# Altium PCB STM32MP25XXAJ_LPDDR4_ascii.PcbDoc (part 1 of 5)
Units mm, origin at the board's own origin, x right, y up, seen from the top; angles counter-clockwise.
Board outline 172 x 137 mm, 4 copper layers (Top Layer, Signal Layer 1, Signal Layer 2, Bottom Layer), stack 1.614 mm thick; 188 components, 294 nets, 1141 pads, 872 vias.
Unrouted connection lines stored in the file: 13.
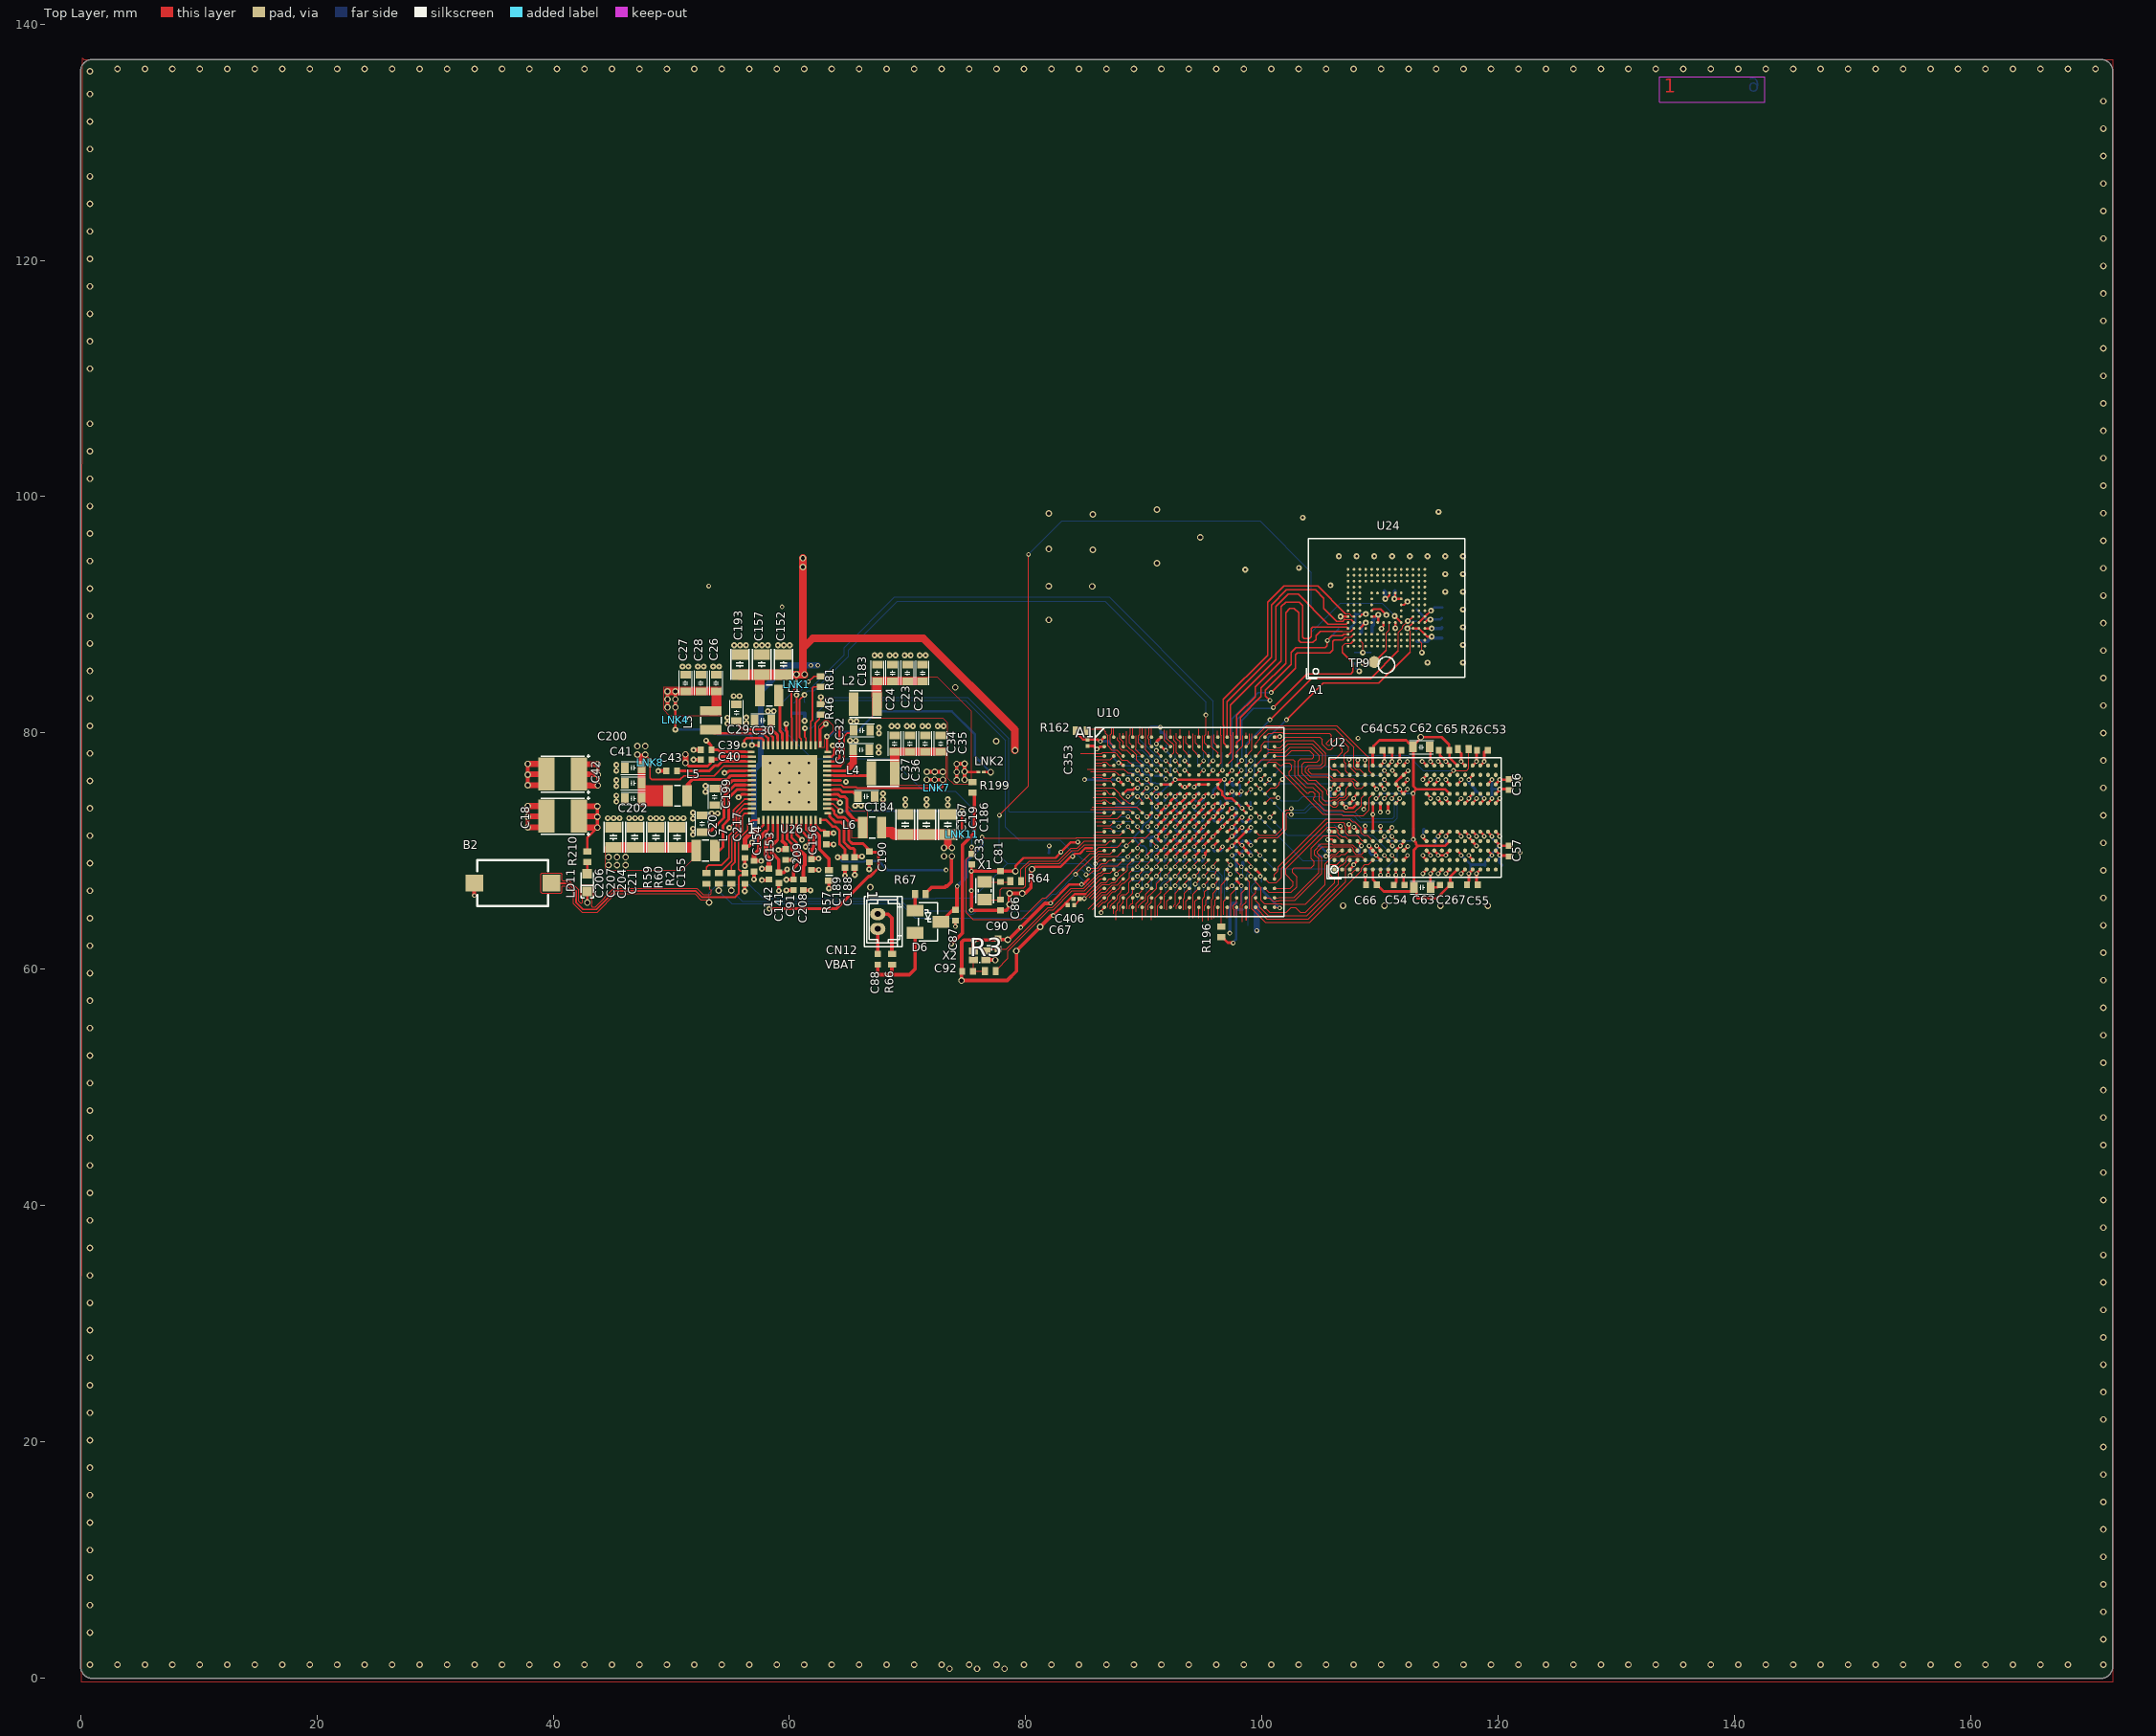
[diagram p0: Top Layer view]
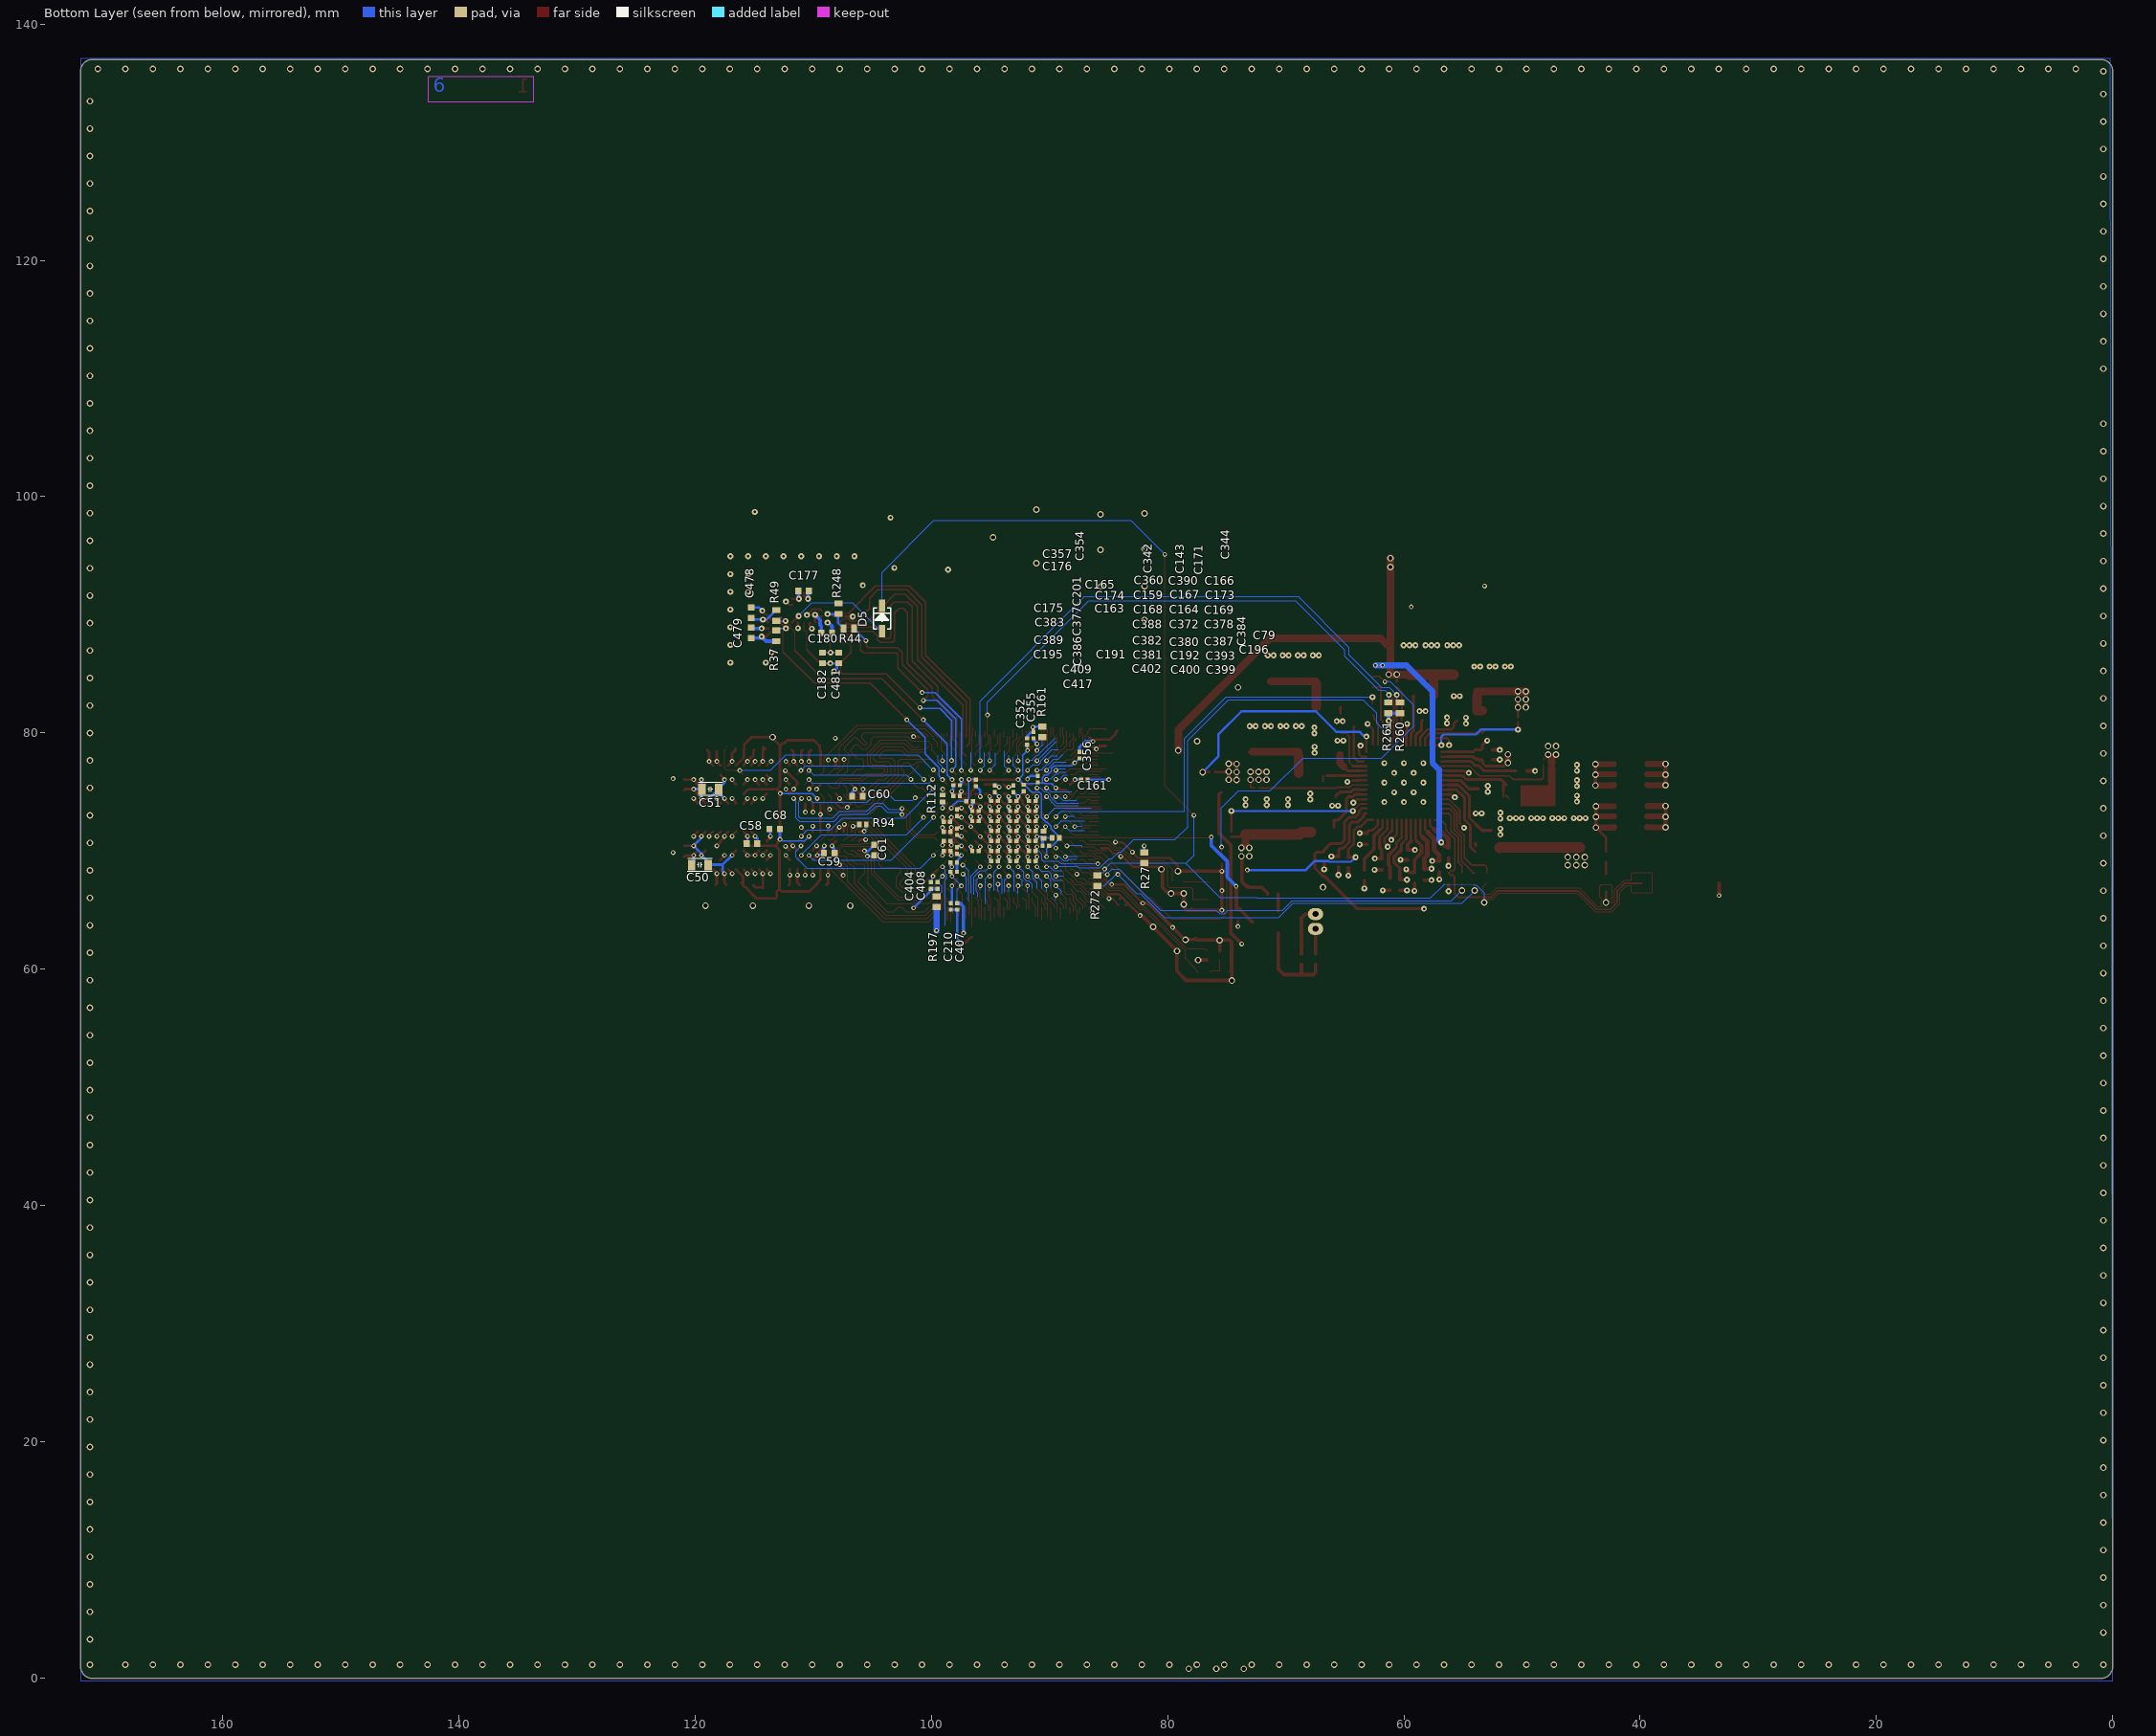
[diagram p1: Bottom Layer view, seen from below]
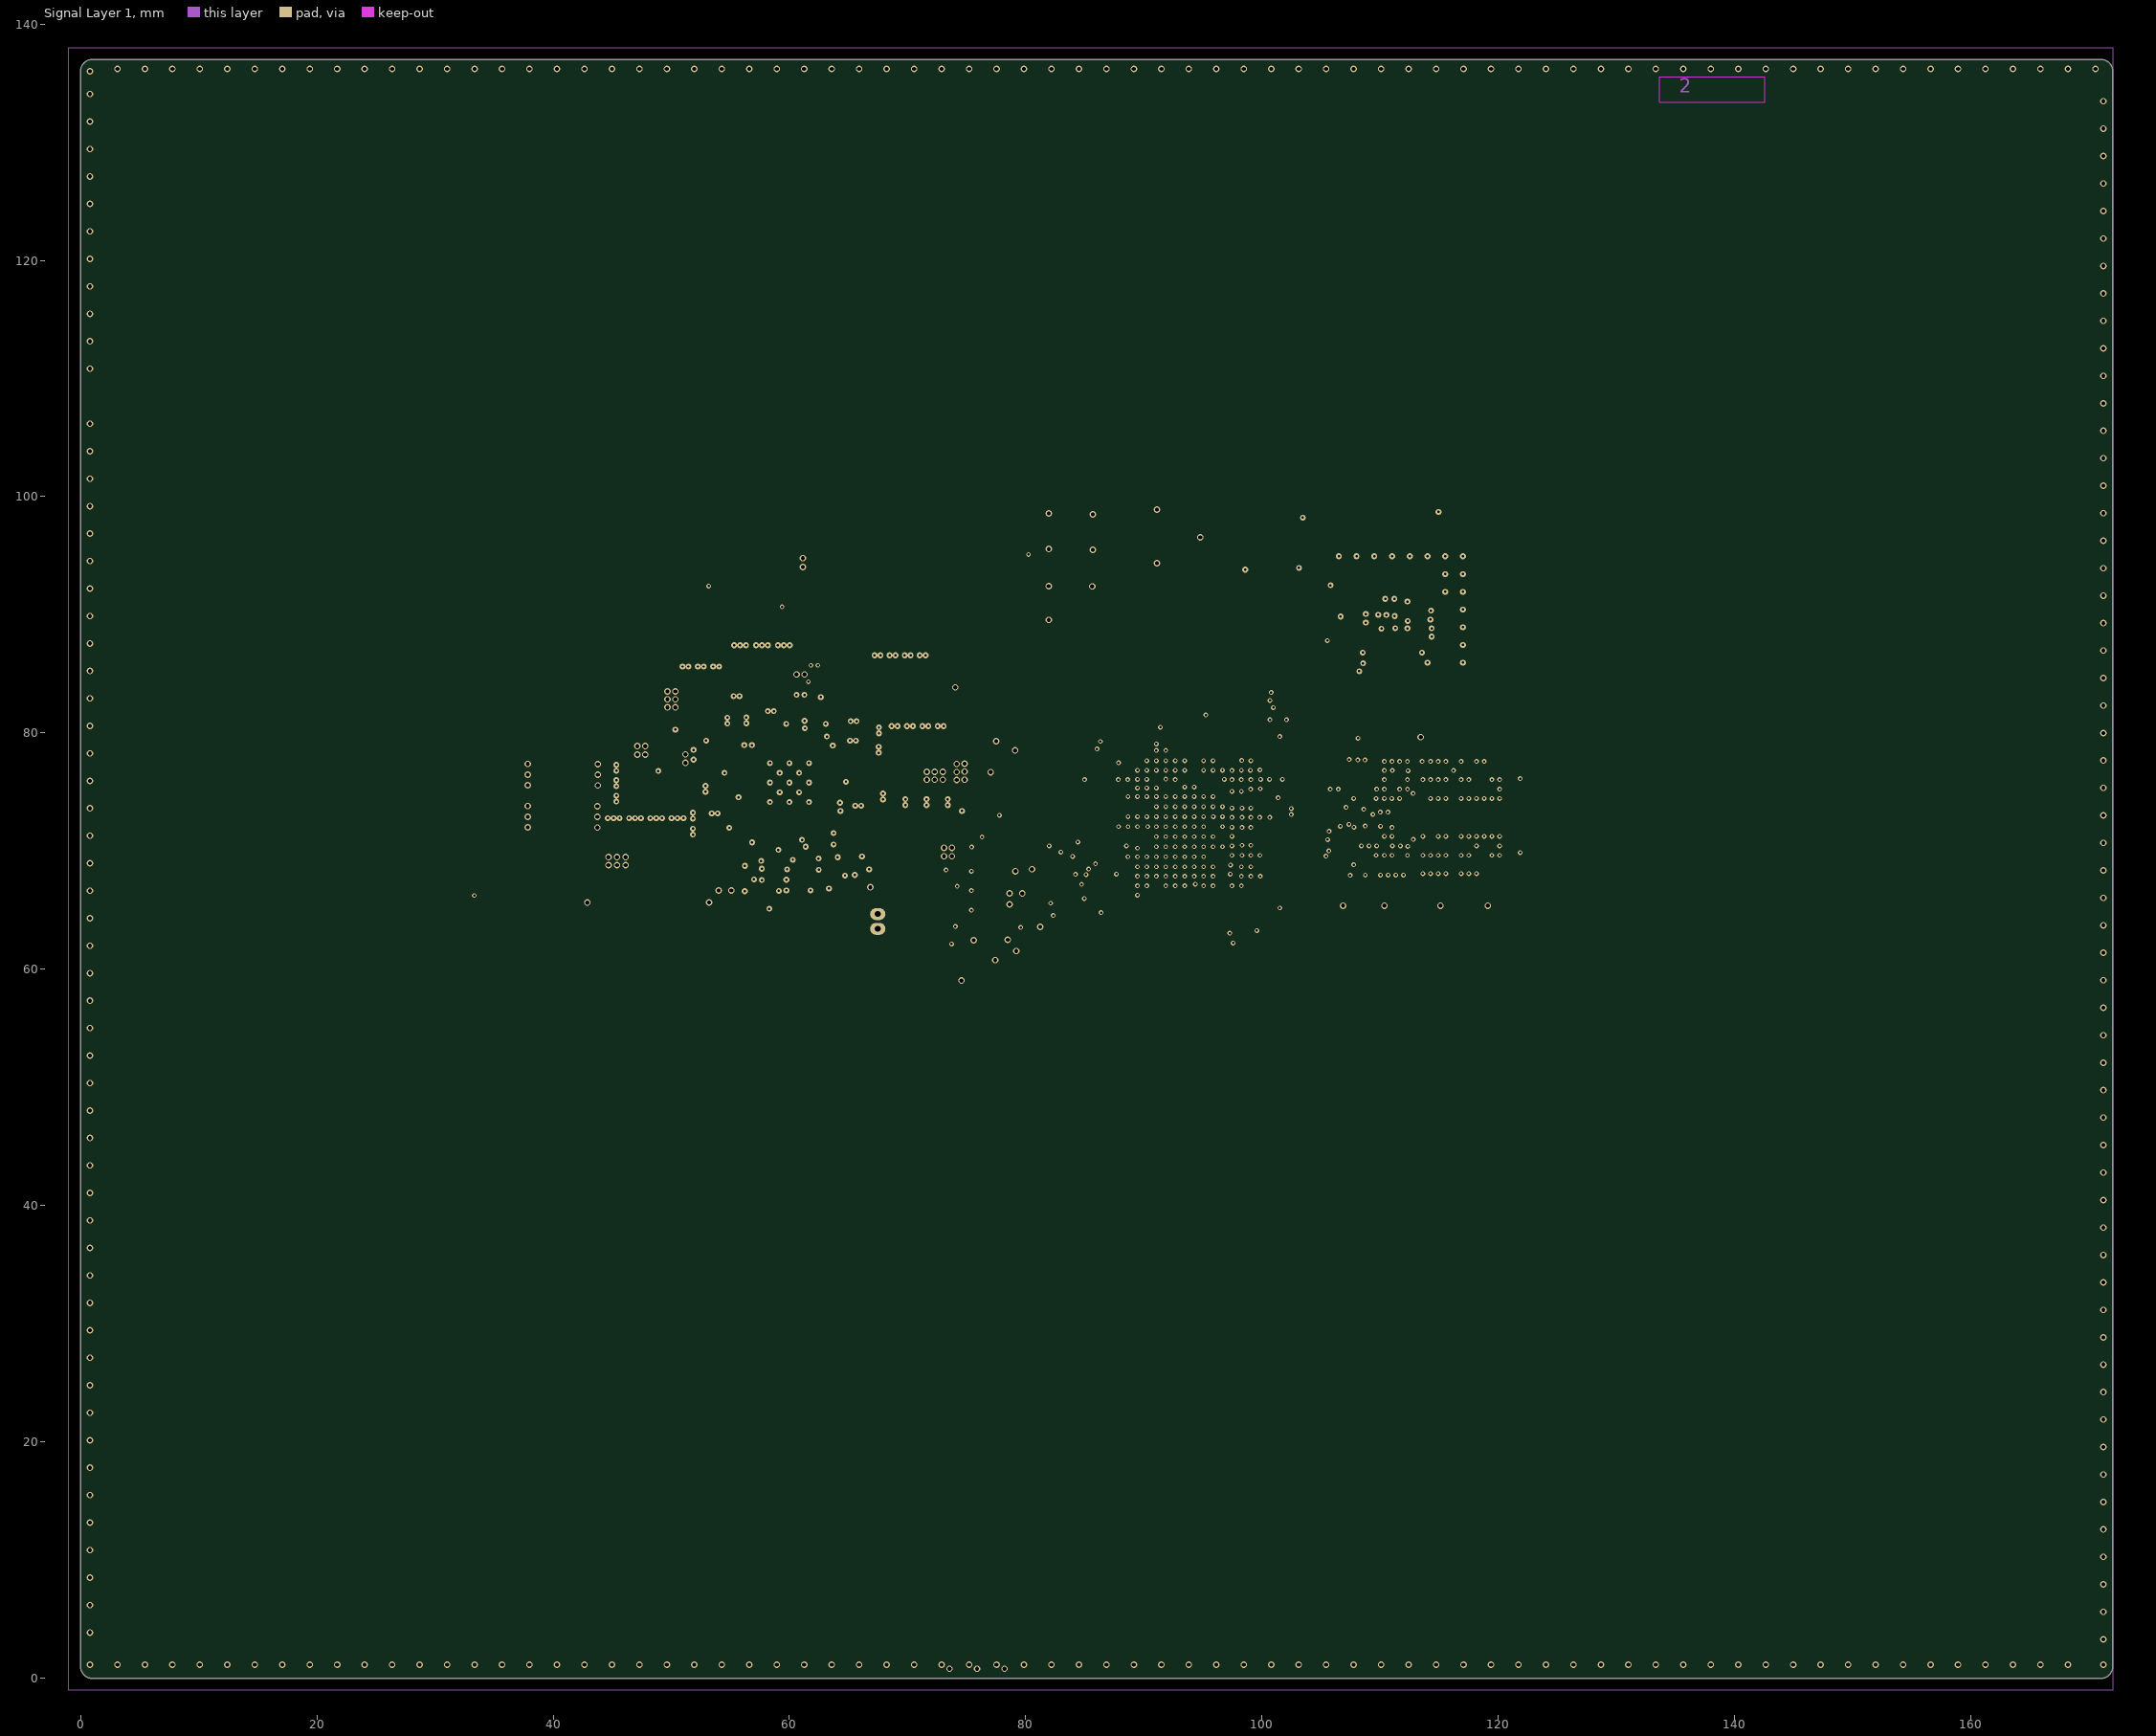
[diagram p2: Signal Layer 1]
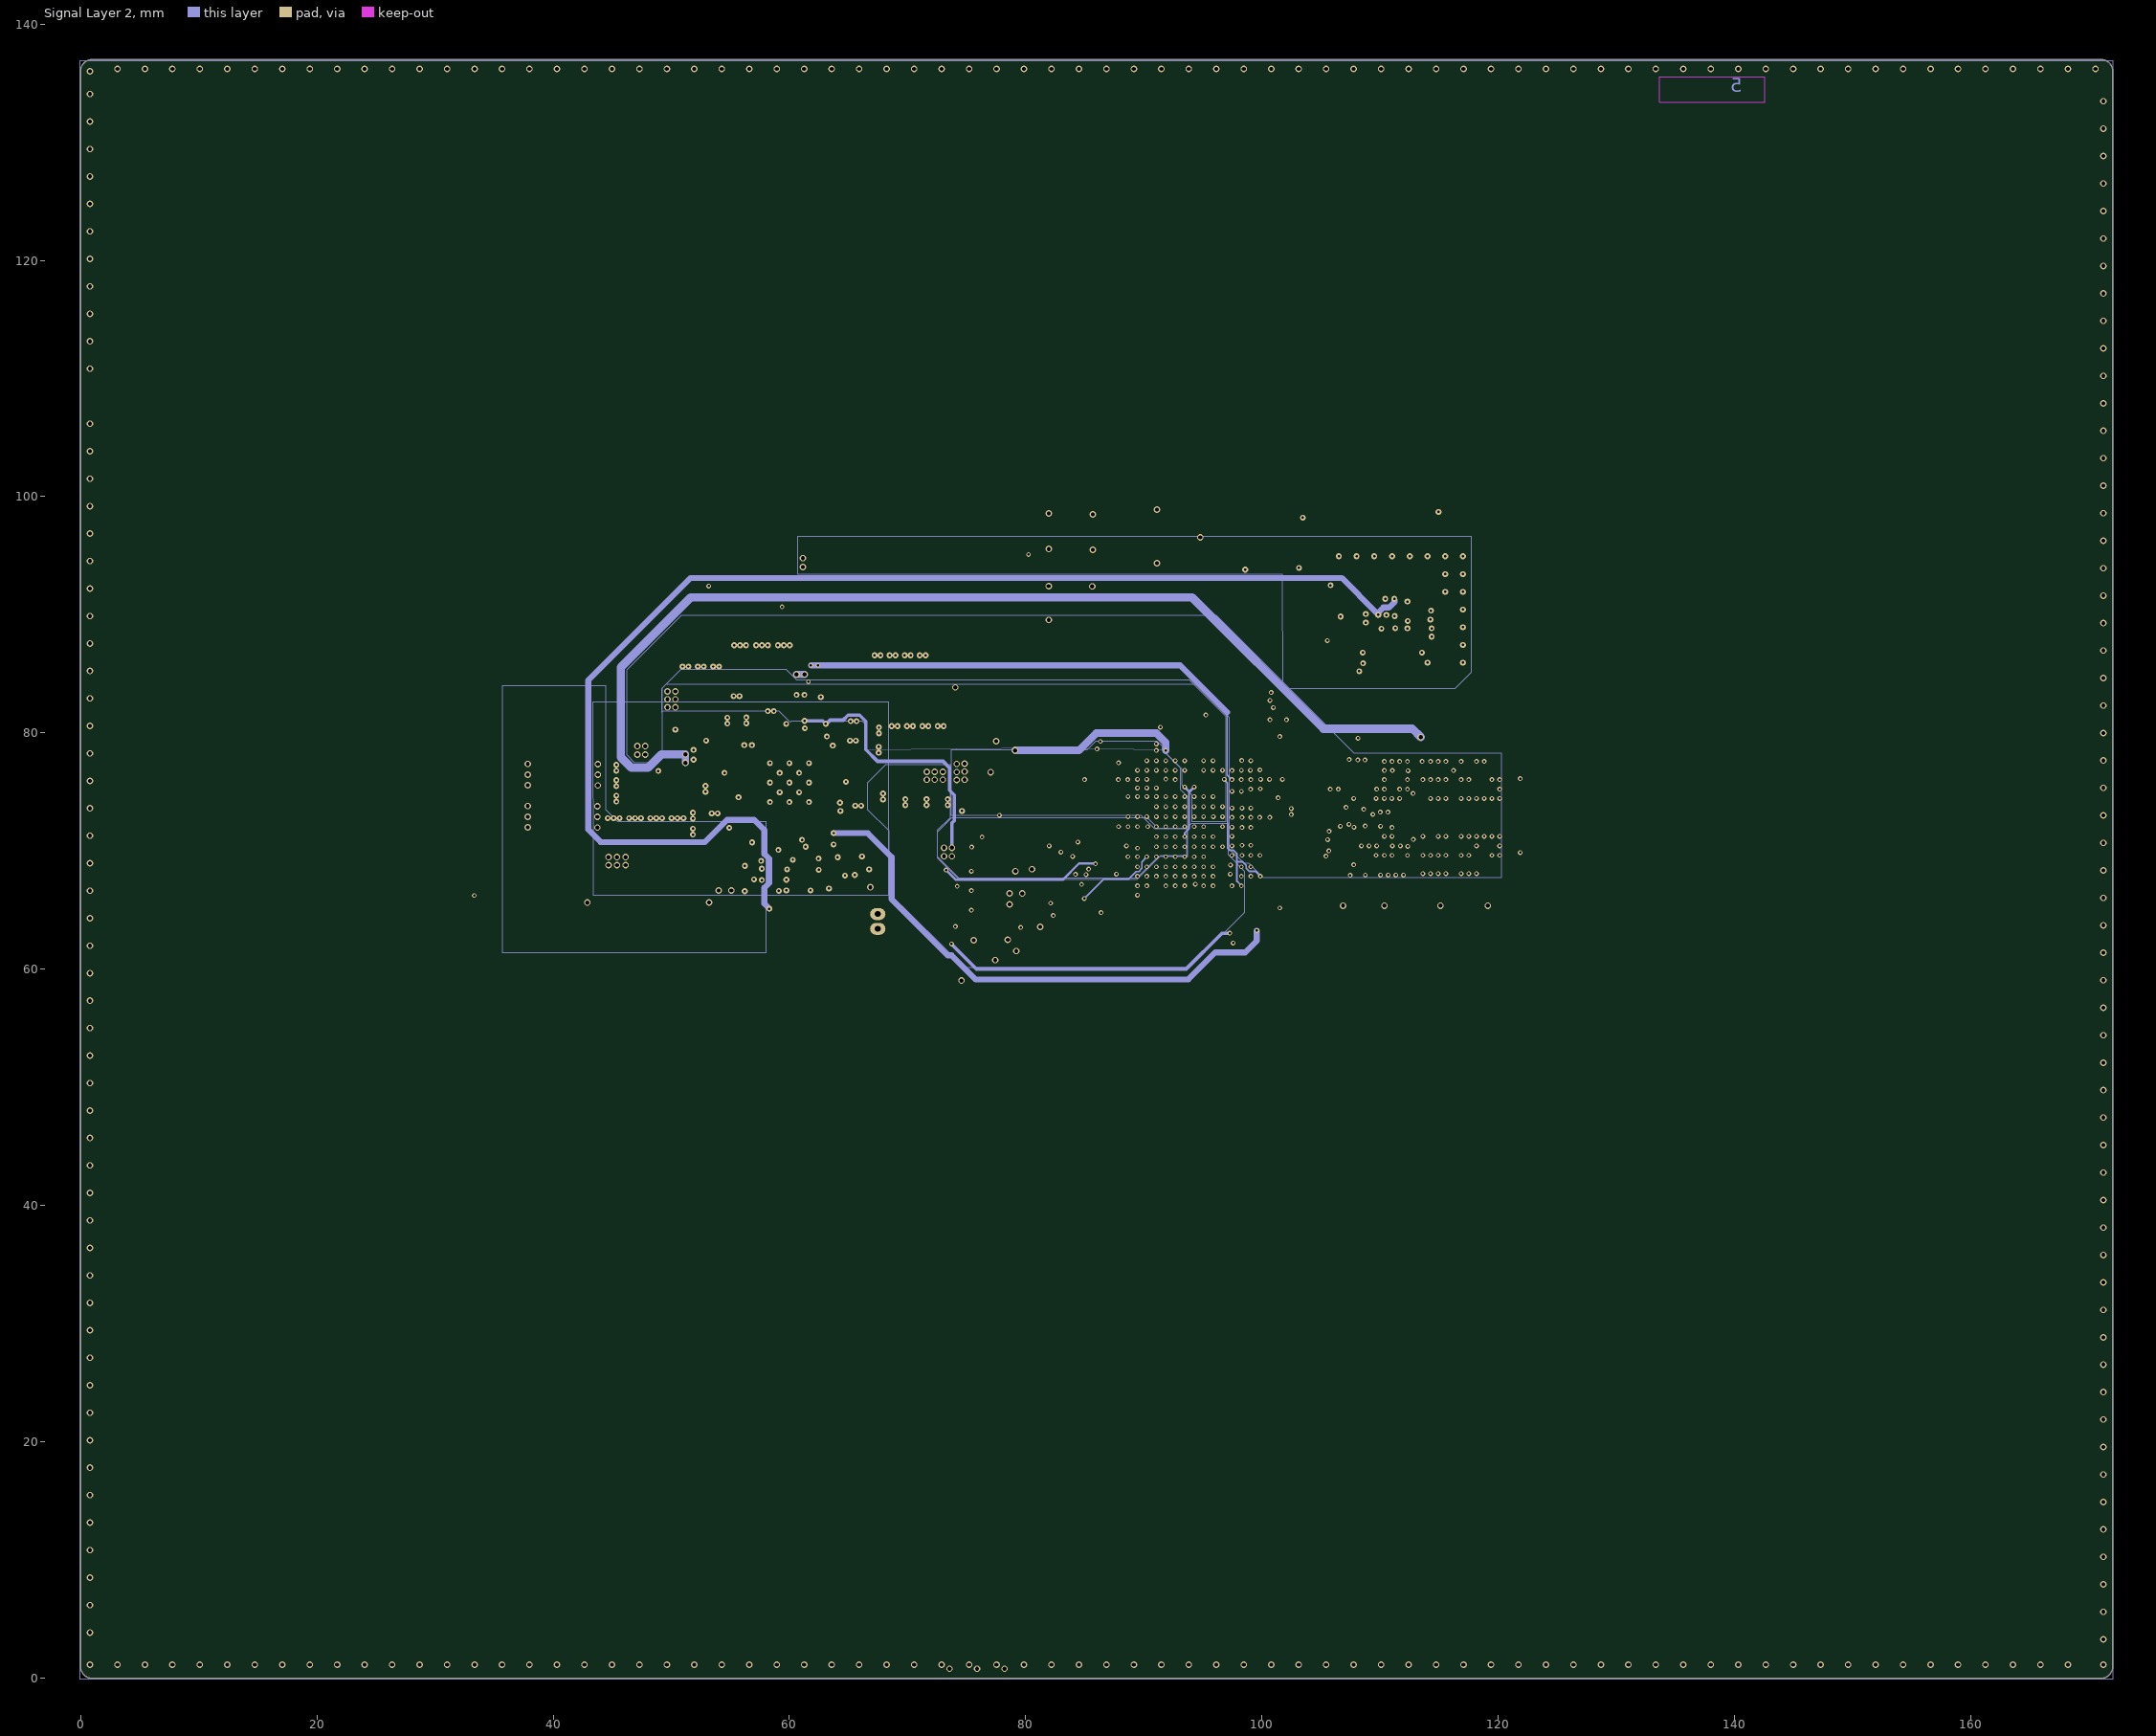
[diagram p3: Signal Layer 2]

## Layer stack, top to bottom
Top Solder: solder mask 0.025, Solder Resist, Dk 3.5
Top Layer: signal copper 0.037
Dielectric 1: prepreg 0.07, Dk 3.8
Signal Layer 1: signal copper 0.035
Dielectric 2: core 1.33, Dk 4.3
Signal Layer 2: signal copper 0.035
Dielectric 3: prepreg 0.07, Dk 3.8
Bottom Layer: signal copper 0.037
Bottom Solder: solder mask 0.025, Solder Resist, Dk 3.5

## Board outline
0,1 0,95 0,136 cw(c1,136) 1,137 171,137 cw(c171,136) 172,136 172,1 cw(c171,1) 171,0 1,0 cw(c1,1)

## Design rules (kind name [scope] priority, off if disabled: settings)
AssemblyTestPointUsage [All] p0: scope1count=1 scope1_0_kind=Board scope1_0_value=Board scope2count=1 scope2_0_kind=Board scope2_0_value=Board commentlength=0
AssemblyTestpoint [All] p0: scope1count=1 scope1_0_kind=Board scope1_0_value=Board scope2count=1 scope2_0_kind=Board scope2_0_value=Board commentlength=0
BoardOutlineClearance Silkscreen [All] p0 off: scope1count=1 scope1_0_kind=Board scope1_0_value=Board scope2count=1 scope2_0_kind=Board scope2_0_value=Board commentlength=90 gap=0 // Protel DXP Scope 1 Expression Was: OnLayer('Top Overlay') or OnLayer('Bottom Overlay')
BoardOutlineClearance [All] p0: scope1count=1 scope1_0_kind=Board scope1_0_value=Board scope2count=1 scope2_0_kind=Board scope2_0_value=Board commentlength=0 gap=0.5
BoardOutlineClearance Silkscreen [OnLayer('Top Overlay') or OnLayer('Bottom Overlay')] p1: gap=0 ignorepadtopadclearanceinfootprint=FALSE
BoardOutlineClearance [All] p2: gap=0.5 ignorepadtopadclearanceinfootprint=FALSE
Clearance Clearance_Default [All] p0: scope1count=1 scope1_0_kind=Board scope1_0_value=Board scope2count=1 scope2_0_kind=Board scope2_0_value=Board commentlength=0 gap=0.1
Clearance Clearance_Default [All] p1: gap=0.1 ignorepadtopadclearanceinfootprint=TRUE except(0: Arc-Hole Track-Hole SMDPad-Hole THPad-Hole Via-Hole Fill-Hole Poly-Hole Region-Hole Text-Hole; 0.09: Arc-SMDPad Track-SMDPad; 0.16: Arc-Arc Arc-Track Track-Track)
ComponentClearance [All] p0 off: scope1count=1 scope1_0_kind=Board scope1_0_value=Board scope2count=1 scope2_0_kind=Board scope2_0_value=Board commentlength=0 gap=0.2 collisioncheckmode=3
ComponentClearance [All] p1 off: gap=0.2 collisioncheckmode=3 verticalgap=0 showdistances=FALSE
DiffPairsRouting DiffPairsRouting_DDR_100R [All] p0 off: scope1count=1 scope1_0_kind=Board scope1_0_value=Board scope2count=1 scope2_0_kind=Board scope2_0_value=Board commentlength=78 // Protel DXP Scope 1 Expression Was: InDifferentialPairClass('DPC_DDR_100R')
DiffPairsRouting DiffPairsRouting_DDR_100R [InDifferentialPairClass('DPC_DDR_100R')] p1: maxlimit=0.16 minlimit=0.14 mostfreqgap=0.254 toplayer_mingap=0.16 toplayer_prefgap=0.16 toplayer_minwidth=0.09 toplayer_maxwidth=0.09 toplayer_prefwidth=0.09 bottomlayer_mingap=0.16 bottomlayer_prefgap=0.16 bottomlayer_minwidth=0.09 bottomlayer_maxwidth=0.09 bottomlayer_prefwidth=0.09 impedanceprofiledriven=TRUE impedanceprofileid={5106416E-43F8-41F8-8BCA-F68B3FB1C141} impedanceprofilevalue=100.000000 maxuncoupledlength=12.7
FabricationTestPointUsage [All] p0: scope1count=1 scope1_0_kind=Board scope1_0_value=Board scope2count=1 scope2_0_kind=Board scope2_0_value=Board commentlength=0 valid=0 allowmultiple=FALSE
FabricationTestpoint [All] p0: scope1count=1 scope1_0_kind=Board scope1_0_value=Board scope2count=1 scope2_0_kind=Board scope2_0_value=Board commentlength=0 side=3 testpointundercomponent=TRUE minsize=1.016 maxsize=2.54 preferedsize=1.524 minholesize=0 maxholesize=1.016 preferedholesize=0.813 testpointgrid=0.025
FanoutControl Fanout_Default [All] p0: scope1count=1 scope1_0_kind=Board scope1_0_value=Board scope2count=1 scope2_0_kind=Board scope2_0_value=Board commentlength=30 // Fanout_Default (Default Rule)
FanoutControl Fanout_Small [All] p0 off: scope1count=1 scope1_0_kind=Board scope1_0_value=Board scope2count=1 scope2_0_kind=Board scope2_0_value=Board commentlength=84 // Protel DXP Scope 1 Expression Was: (CompPinCount < 5)   Fanout_Small (Default Rule)
FanoutControl Fanout_SOIC [All] p0 off: scope1count=1 scope1_0_kind=Board scope1_0_value=Board scope2count=1 scope2_0_kind=Board scope2_0_value=Board commentlength=71 // Protel DXP Scope 1 Expression Was: IsSOIC   Fanout_SOIC (Default Rule)
FanoutControl Fanout_LCC [All] p0 off: scope1count=1 scope1_0_kind=Board scope1_0_value=Board scope2count=1 scope2_0_kind=Board scope2_0_value=Board commentlength=69 // Protel DXP Scope 1 Expression Was: IsLCC   Fanout_LCC (Default Rule)
FanoutControl Fanout_BGA [All] p0 off: scope1count=1 scope1_0_kind=Board scope1_0_value=Board scope2count=1 scope2_0_kind=Board scope2_0_value=Board commentlength=69 // Protel DXP Scope 1 Expression Was: IsBGA   Fanout_BGA (Default Rule)
FanoutControl Fanout_BGA [IsBGA] p1: bgadir=Out bgaviamode=Closest fanoutstyle=Auto fanoutdirection=Alternating viagrid=0.025 // Fanout_BGA (Default Rule)
FanoutControl Fanout_LCC [IsLCC] p2: bgadir=Out bgaviamode=Closest fanoutstyle=Auto fanoutdirection=Alternating viagrid=0.025 // Fanout_LCC (Default Rule)
FanoutControl Fanout_SOIC [IsSOIC] p3: bgadir=Out bgaviamode=Closest fanoutstyle=Auto fanoutdirection=Alternating viagrid=0.025 // Fanout_SOIC (Default Rule)
FanoutControl Fanout_Small [(CompPinCount < 5)] p4: bgadir=Out bgaviamode=Closest fanoutstyle=Auto fanoutdirection=OutThenIn viagrid=0.025 // Fanout_Small (Default Rule)
FanoutControl Fanout_Default [All] p5: bgadir=Out bgaviamode=Closest fanoutstyle=Auto fanoutdirection=Alternating viagrid=0.025 // Fanout_Default (Default Rule)
Height [All] p0: scope1count=1 scope1_0_kind=Board scope1_0_value=Board scope2count=1 scope2_0_kind=Board scope2_0_value=Board commentlength=0
HoleSize [All] p0: scope1count=1 scope1_0_kind=Board scope1_0_value=Board scope2count=1 scope2_0_kind=Board scope2_0_value=Board commentlength=0 absolutevalues=TRUE maxlimit=10 minlimit=0.025 maxpercent=80.000 minpercent=20.000
HoleSize [All] p1: absolutevalues=TRUE maxlimit=10 minlimit=0.025 maxpercent=80.000 minpercent=20.000
HoleToHoleClearance [All] p0: scope1count=1 scope1_0_kind=Board scope1_0_value=Board scope2count=1 scope2_0_kind=Board scope2_0_value=Board commentlength=0
HoleToHoleClearance [All] p1: gap=0.25 allowstackedmicrovias=TRUE
LayerPairs [All] p0: scope1count=1 scope1_0_kind=Board scope1_0_value=Board scope2count=1 scope2_0_kind=Board scope2_0_value=Board commentlength=0 enforce=TRUE
Length Length__SINGLE_SDMMC2_50R [All] p0: scope1count=1 scope1_0_kind=NetClass scope1_0_value=NC_SINGLE_SDMMC2_50R scope2count=1 scope2_0_kind=Board scope2_0_value=Board commentlength=0 maxlimit=50 minlimit=0
Length Length__SINGLE_SDMMC2_50R [InNetClass('NC_SINGLE_SDMMC2_50R')] p1: maxlimit=50 minlimit=0
MinimumSolderMaskSliver [All] p0: scope1count=1 scope1_0_kind=Board scope1_0_value=Board scope2count=1 scope2_0_kind=Board scope2_0_value=Board commentlength=0
MinimumSolderMaskSliver [All] p1: minsoldermaskwidth=0.07
NetAntennae [All] p0: scope1count=1 scope1_0_kind=Board scope1_0_value=Board scope2count=1 scope2_0_kind=Board scope2_0_value=Board commentlength=0
PasteMaskExpansion [All] p0: scope1count=1 scope1_0_kind=Board scope1_0_value=Board scope2count=1 scope2_0_kind=Board scope2_0_value=Board commentlength=0 expansion=0
PlaneClearance [All] p0: scope1count=1 scope1_0_kind=Board scope1_0_value=Board scope2count=1 scope2_0_kind=Board scope2_0_value=Board commentlength=0 clearance=0.508
PlaneConnect [All] p0: scope1count=1 scope1_0_kind=Board scope1_0_value=Board scope2count=1 scope2_0_kind=Board scope2_0_value=Board commentlength=0 planeconnectstyle=Direct reliefexpansion=0.508 reliefentries=4 reliefconductorwidth=0.21 reliefairgap=0.21
PlaneConnect [All] p1: planeconnectstyle=Direct reliefexpansion=0.508 reliefentries=4 reliefconductorwidth=0.21 reliefairgap=0.21
PolygonConnect PolygonConnect_Default [All] p0: scope1count=1 scope1_0_kind=Board scope1_0_value=Board scope2count=1 scope2_0_kind=Board scope2_0_value=Board commentlength=0 connectstyle=Direct reliefconductorwidth=0.25 reliefentries=4 polygonreliefangle="90 Angle"
PolygonConnect PolygonConnect_Default [All] p1: connectstyle=Direct reliefconductorwidth=0.25 reliefentries=4 polygonreliefangle="90 Angle" airgapwidth=0.25
RoomDefinition U_LPDDR4_16bits [All] p0: scope1count=1 scope1_0_kind=ComponentClass scope1_0_value=U_LPDDR4_16bits scope2count=1 scope2_0_kind=Board scope2_0_value=Board commentlength=0 region_x1=157300983 region_y1=77395509 region_x2=174919953 region_y2=80407467 confinementstyle=ConfineIn
RoomDefinition U_PMIC [All] p0: scope1count=1 scope1_0_kind=ComponentClass scope1_0_value=U_PMIC scope2count=1 scope2_0_kind=Board scope2_0_value=Board commentlength=0 region_x1=0 region_y1=0 region_x2=20000000 region_y2=10000000 confinementstyle=ConfineIn
RoomDefinition U_eMMC [All] p0: scope1count=1 scope1_0_kind=ComponentClass scope1_0_value=U_eMMC scope2count=1 scope2_0_kind=Board scope2_0_value=Board commentlength=0 region_x1=0 region_y1=0 region_x2=20000000 region_y2=10000000 confinementstyle=ConfineIn
RoomDefinition U_LPDDR4_16bits [InComponentClass('U_LPDDR4_16bits')] p1: confinementstyle=ConfineIn formatcopy=TRUE lockcomponents=FALSE outline 173.145,1.412 217.897,1.412 217.897,9.062 173.145,9.062
RoomDefinition U_PMIC [InComponentClass('U_PMIC')] p2: confinementstyle=ConfineIn formatcopy=TRUE lockcomponents=FALSE outline -226.399,-195.173 -175.599,-195.173 -175.599,-169.773 -226.399,-169.773
RoomDefinition U_eMMC [InComponentClass('U_eMMC')] p3: confinementstyle=ConfineIn formatcopy=TRUE lockcomponents=FALSE outline -226.399,-195.173 -175.599,-195.173 -175.599,-169.773 -226.399,-169.773
RoutingCorners [All] p0: scope1count=1 scope1_0_kind=Board scope1_0_value=Board scope2count=1 scope2_0_kind=Board scope2_0_value=Board commentlength=0 cornerstyle=45-Degree minsetback=2.54 maxsetback=2.54
RoutingLayers [All] p0: scope1count=1 scope1_0_kind=Board scope1_0_value=Board scope2count=1 scope2_0_kind=Board scope2_0_value=Board commentlength=0 top layer=Automatic mid layer 1=Automatic mid layer 4=Automatic bottom layer=Automatic
RoutingPriority [All] p0: scope1count=1 scope1_0_kind=Board scope1_0_value=Board scope2count=1 scope2_0_kind=Board scope2_0_value=Board commentlength=0
RoutingTopology [All] p0: scope1count=1 scope1_0_kind=Board scope1_0_value=Board scope2count=1 scope2_0_kind=Board scope2_0_value=Board commentlength=0 topology=Shortest
RoutingVias RoutingVias_Default [All] p0: scope1count=1 scope1_0_kind=Board scope1_0_value=Board scope2count=1 scope2_0_kind=Board scope2_0_value=Board commentlength=0 holewidth=0.15 width=0.4 viastyle="Through Hole" minholewidth=0.15 minwidth=0.4 maxholewidth=0.35 maxwidth=0.6
RoutingVias RoutingVias_Default [All] p1: holewidth=0.15 width=0.4 viastyle="Through Hole" minholewidth=0.15 minwidth=0.4 maxholewidth=0.35 maxwidth=0.6 viatemplateguid#1={A479BBDC-94B7-4D18-B59D-B7A18B767B5F} viatemplateguid#2={564DD7E2-F718-4BCE-8A99-5417C9FECCB6} viatemplateguid#3={BA919398-BDEC-4FED-AED0-6BF9ED2A8C2F} viatemplateguid#4={BB8F4C89-420F-4EBC-9772-FD82009DE81A} viatemplateguid#5={3FF096CA-B7A5-4E0B-A50A-8B2CD18CCC19} viatemplatename#1=v55h35m40mx40 viatemplatename#2=v40h20m0mx0 viatemplatename#3=v50h25m30mx30 viatemplatename#4=v40h20m25mx25 viatemplatename#5=v50h25m0mx0
ShortCircuit ShortCircuit_Link200 [All] p0: scope1count=1 scope1_0_kind=PadClass scope1_0_value=PC_LINK200 scope2count=1 scope2_0_kind=Board scope2_0_value=Board commentlength=0 allowed=TRUE
ShortCircuit ShortCircuit_Link200 [InPadClass('PC_LINK200')] p1: allowed=TRUE
SilkToBoardRegionClearance [All] p0: scope1count=1 scope1_0_kind=Board scope1_0_value=Board scope2count=1 scope2_0_kind=Board scope2_0_value=Board commentlength=0
SilkToSilkClearance [All] p0: scope1count=1 scope1_0_kind=Board scope1_0_value=Board scope2count=1 scope2_0_kind=Board scope2_0_value=Board commentlength=0
SilkToSilkClearance [All] p1: silktosilkclearance=0.2
SilkToSolderMaskClearance [All] p0 off: scope1count=1 scope1_0_kind=Board scope1_0_value=Board scope2count=1 scope2_0_kind=Board scope2_0_value=Board commentlength=44 // Protel DXP Scope 1 Expression Was: IsPad
SilkToSolderMaskClearance [IsPad] p1: minsilkscreentomaskgap=0.015 clearancetoexposedcopper=TRUE
SolderMaskExpansion [All] p0: scope1count=1 scope1_0_kind=Board scope1_0_value=Board scope2count=1 scope2_0_kind=Board scope2_0_value=Board commentlength=0 expansion=0.1
SolderMaskExpansion [All] p1: expansion=0.1 istentingtop=FALSE
UnRoutedNet [All] p0: scope1count=1 scope1_0_kind=Board scope1_0_value=Board scope2count=1 scope2_0_kind=Board scope2_0_value=Board commentlength=0
UnpouredPolygon [All] p0: scope1count=1 scope1_0_kind=Board scope1_0_value=Board scope2count=1 scope2_0_kind=Board scope2_0_value=Board commentlength=0
ViasUnderSMD [All] p0: scope1count=1 scope1_0_kind=PadClass scope1_0_value=PC_VIAS-IN-PAD_OK scope2count=1 scope2_0_kind=Board scope2_0_value=Board commentlength=0 allowed=TRUE
ViasUnderSMD [InPadClass('PC_VIAS-IN-PAD_OK')] p1: allowed=TRUE
Width Width_Default [All] p0: scope1count=1 scope1_0_kind=NetClass scope1_0_value="All Nets" scope2count=1 scope2_0_kind=Board scope2_0_value=Board commentlength=0 maxlimit=10 minlimit=0.09 preferedwidth=0.11
Width Width_Default [InNetClass('All Nets')] p1: maxlimit=10 minlimit=0.09 preferedwidth=0.11 minimp=50.000000 maximp=50.000000 favimp=50.000000
16 further rules are at their usual default settings.

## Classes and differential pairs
component class U_LPDDR4_16bits: C50 C51 C52 C53 C54 C55 C56 C57 C58 C59 C60 C61 C62 C63 C64 C65 C66 C68 C267 R26 R94 R112 U2
net class eMMC.SDMMC2_D[0..7]: eMMC.SDMMC2_D0 eMMC.SDMMC2_D1 eMMC.SDMMC2_D2 eMMC.SDMMC2_D3 eMMC.SDMMC2_D4 eMMC.SDMMC2_D5 eMMC.SDMMC2_D6 eMMC.SDMMC2_D7
component class "U_STM32MP25XXAJ Power": C67 C79 C87 C88 C143 C159 C161 C163 C164 C165 C166 C167 C168 C169 C171 C173 C174 C175 C176 C191 C192 C195 C196 C201 C210 C342 C344 C352 C353 C354 C355 C356 C357 C360 C372 C377 C378 C380 C381 C382 C383 C384 C386 C387 C388 C389 C390 C393 C399 C400 C402 C404 C406 C407 C408 C409 C417 CN12 D6 R66 R67 R197 R199
component class "U_STM32MP25XXAJ I_Os": C33 C81 C86 C90 C92 R3 R27 R64 R161 R162 R196 R260 R261 R272 U10 X1 X2
component class U_PMIC: B2 C18 C19 C20 C21 C22 C23 C24 C26 C27 C28 C29 C30 C32 C34 C35 C36 C37 C38 C39 C40 C41 C42 C43 C91 C141 C142 C152 C153 C154 C155 C156 C157 C183 C184 C186 C187 C188 C189 C190 C193 C199 C200 C202 C204 C206 C207 C208 C209 C217 L1 L2 L3 L4 L5 L6 L7 LD11 LNK1 LNK2 LNK4 LNK7 LNK8 LNK11 R2 R46 R57 R59 R60 R81 R210 U26
component class U_eMMC: C177 C180 C182 C478 C479 C481 D5 R37 R44 R49 R248 TP9 U24
differential pair DDR_DQS1: +DDR_DQS1_P -DDR_DQS1_N
differential pair DDR_DQS0: +DDR_DQS0_P -DDR_DQS0_N
differential pair " ": +DDR_CLK_P -DDR_CLK_N

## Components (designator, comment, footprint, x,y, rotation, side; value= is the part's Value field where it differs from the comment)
B2 "SW_PUSH_SMD_2P" SWI_WE_434121025816 36.59,67.295 r0 top
C18 "Cap_POL_TANA" CPOL_TCJ-B_1210_H210 40.812,72.961 r180 top
C19 "Capacitor" C0805 71.6,72.25 r270 top
C20 "Capacitor" C0603 52.6,72.325 r270 top
C21 "Capacitor" C0805 50.5,71.173 r270 top
C22 "Capacitor" C0603 71.275,85.075 r270 top
C23 "Capacitor" C0603 70,85.075 r270 top
C24 "Capacitor" C0603 68.725,85.075 r270 top
C26 "Capacitor" C0603 53.8,84.225 r270 top
C27 "Capacitor" C0603 51.2,84.225 r270 top
C28 "Capacitor" C0603 52.5,84.225 r270 top
C29 "Capacitor" C0603 55.525,81.725 r270 top
C30 "Capacitor" C0603 57.75,81.075 r0 top
C32 "Capacitor" C0603 66.125,80.225 r180 top
C33 "Capacitor" C0402 75.425,69.325 r90 top
C34 "Capacitor" C0603 71.5,79.1 r270 top
C35 "Capacitor" C0603 72.8,79.1 r270 top
C36 "Capacitor" C0603 70.2,79.1 r270 top
C37 "Capacitor" C0603 68.9,79.1 r270 top
C38 "Capacitor" C0603 66.075,78.575 r180 top
C39 "Capacitor" C0402 52.945,78.575 r0 top
C40 "Capacitor" C0402 52.945,77.75 r0 top
C41 "Capacitor" C0603 46.775,75.75 r0 top
C42 "Cap_POL_TANA" CPOL_TCJ-B_1210_H210 40.812,76.523 r180 top
C43 "Capacitor" C0402 50.035,76.8 r0 top
C50 "Capacitor" C0603 119.575,68.825 r180 bottom
C51 "Capacitor" C0603 118.7,75.25 r0 bottom
C52 "Capacitor" C0402 111.35,78.55 r180 top
C53 "Capacitor" C0402 118.65,78.525 r0 top
C54 "Capacitor" C0402 111.6,67.135 r180 top
C55 "Capacitor" C0402 117.8,67.15 r0 top
C56 "Capacitor" C0402 120.9,75.625 r90 top
C57 "Capacitor" C0402 120.9,70 r270 top
C58 "Capacitor" C0402 115.175,70.65 r0 bottom
C59 "Capacitor" C0402 108.625,69.825 r180 bottom
C60 "Capacitor" C0402 106.25,74.65 r180 bottom
C61 "Capacitor" C0402 104.8,70.1 r90 bottom
C62 "Capacitor" C0603 113.475,78.8 r180 top
C63 "Capacitor" C0603 113.55,66.92 r180 top
C64 "Capacitor" C0402 109.75,78.55 r180 top
C65 "Capacitor" C0402 115.4,78.55 r0 top
C66 "Capacitor" C0402 109.25,67.15 r0 top
C67 "Capacitor" C0201_MURATA_GRM033_H0P3 83.825,65.425 r0 top
C68 "Capacitor" C0402 113.25,71.875 r180 bottom
C79 "Capacitor" C0201_H0P5 89.45,71.125 r180 bottom
C81 "Capacitor" C0402 77.85,67.85 r90 top
C86 "Capacitor" C0402 77.85,65.45 r270 top
C87 "" C0402 74.05,64.575 r90 top
C88 "Capacitor" C0402 67.475,60.85 r270 top
C90 "Capacitor" C0402 77.65,62.15 r270 top
C91 "Capacitor" C0402 60.345,67.16 r270 top
C92 "Capacitor" C0402 75.075,59.825 r180 top
C141 "Capacitor" C0402 59.1,67.75 r270 top
C142 "Capacitor" C0402 58.275,68.06 r270 top
C143 "Capacitor" C0201_MURATA_GRM033_H0P3 93.05,75.275 r90 bottom
C152 "Capacitor" C0805 59.5,85.8 r270 top
C153 "Capacitor" C0402 59.675,69.72 r90 top
C154 "Capacitor" C0402 57,68.725 r90 top
C155 "Capacitor" C0402 56.227,67.695 r90 top
C156 "Capacitor" C0402 63.125,71.02 r90 top
C157 "Capacitor" C0805 57.65,85.8 r270 top
C159 "Capacitor" C0201_MURATA_GRM033_H0P3 94.65,73.4 r180 bottom
C161 "Capacitor" C0201_MURATA_GRM033_H0P3 87.05,76.05 r0 bottom
C163 "Capacitor" C0201_MURATA_GRM033_H0P3 96.25,72.55 r0 bottom
C164 "Capacitor" C0201_MURATA_GRM033_H0P3 93.05,72.55 r180 bottom
C165 "Capacitor" C0201_MURATA_GRM033_H0P3 96.75,74.225 r0 bottom
C166 "Capacitor" C0201_MURATA_GRM033_H0P3 91.45,74.25 r0 bottom
C167 "Capacitor" C0201_MURATA_GRM033_H0P3 93.05,73.4 r180 bottom
C168 "Capacitor" C0201_MURATA_GRM033_H0P3 94.65,72.55 r0 bottom
C169 "Capacitor" C0201_MURATA_GRM033_H0P3 91.45,72.55 r0 bottom
C171 "Capacitor" C0201_MURATA_GRM033_H0P3 92.175,75.35 r90 bottom
C173 "Capacitor" C0201_MURATA_GRM033_H0P3 91.45,73.4 r0 bottom
C174 "Capacitor" C0201_MURATA_GRM033_H0P3 96.25,73.4 r0 bottom
C175 "Capacitor" C0201_MURATA_GRM033_H0P3 98.675,72.475 r180 bottom
C176 "Capacitor" C0201_MURATA_GRM033_H0P3 97.85,74.675 r180 bottom
C177 "Capacitor" C0402 110.8,92.025 r0 bottom
C180 "Capacitor" C0402 108.85,88.475 r0 bottom
C182 "Capacitor" C0402 107.825,86.35 r90 bottom
C183 "Capacitor" C0603 67.45,85.075 r270 top
C184 "Capacitor" C0603 66.497,74.625 r180 top
C186 "Capacitor" C0805 73.4,72.25 r270 top
C187 "Capacitor" C0805 69.8,72.25 r270 top
C188 "Capacitor" C0402 65.525,69.04 r90 top
C189 "Capacitor" C0402 64.7,69.04 r90 top
C190 "Capacitor" C0402 66.75,69.515 r270 top
C191 "Capacitor" C0201_MURATA_GRM033_H0P3 96.25,70 r0 bottom
C192 "Capacitor" C0201_MURATA_GRM033_H0P3 93.05,70 r180 bottom
C193 "Capacitor" C0805 55.8,85.8 r270 top
C195 "Capacitor" C0201_MURATA_GRM033_H0P3 98.65,70.025 r0 bottom
C196 "Capacitor" C0201_MURATA_GRM033_H0P3 90.3,70.45 r180 bottom
C199 "Capacitor" C0603 53.675,74.6 r90 top
C200 "Capacitor" C0603 46.775,77.05 r0 top
C201 "Capacitor" C0201_MURATA_GRM033_H0P3 97.825,73.25 r90 bottom
C202 "Capacitor" C0603 46.775,74.45 r0 top
C204 "Capacitor" C0805 48.7,71.173 r270 top
C206 "Capacitor" C0805 45.1,71.173 r270 top
C207 "Capacitor" C0805 46.9,71.173 r270 top
C208 "Capacitor" C0402 61.17,67.16 r270 top
C209 "Capacitor" C0402 61.85,68.87 r90 top
C210 "Capacitor" C0201_MURATA_GRM033_H0P3 98.35,65.325 r90 bottom
C217 "Capacitor" C0402 56.225,69.87 r270 top
C267 "Capacitor" C0402 115.5,67.135 r0 top
C342 "Capacitor" C0201_MURATA_GRM033_H0P3 94.625,75.275 r90 bottom
C344 "Capacitor" C0201_MURATA_GRM033_H0P3 90.975,76.1 r270 bottom
C352 "Capacitor" C0201_MURATA_GRM033_H0P3 91.9,79.275 r270 bottom
C353 "Capacitor" C0201_MURATA_GRM033_H0P3 85.225,79.175 r270 top
C354 "Capacitor" C0201_MURATA_GRM033_H0P3 96.225,75.775 r90 bottom
C355 "Capacitor" C0201_MURATA_GRM033_H0P3 91.35,79.825 r270 bottom
C356 "Capacitor" C0201_MURATA_GRM033_H0P3 87.45,78.125 r270 bottom
C357 "Capacitor" C0201_MURATA_GRM033_H0P3 97.85,75.575 r180 bottom
C360 "Capacitor" C0201_MURATA_GRM033_H0P3 94.65,74.25 r180 bottom
C372 "Capacitor" C0201_MURATA_GRM033_H0P3 93.05,71.7 r180 bottom
C377 "Capacitor" C0201_MURATA_GRM033_H0P3 97.825,71.65 r90 bottom
C378 "Capacitor" C0201_MURATA_GRM033_H0P3 91.45,71.7 r180 bottom
C380 "Capacitor" C0201_MURATA_GRM033_H0P3 93.05,70.85 r0 bottom
C381 "Capacitor" C0201_MURATA_GRM033_H0P3 94.65,70 r180 bottom
C382 "Capacitor" C0201_MURATA_GRM033_H0P3 94.65,70.85 r0 bottom
C383 "Capacitor" C0201_MURATA_GRM033_H0P3 98.65,71.625 r0 bottom
C384 "Capacitor" C0201_H0P5 90.5,71.375 r90 bottom
C386 "Capacitor" C0201_MURATA_GRM033_H0P3 97.825,70.05 r90 bottom
C387 "Capacitor" C0201_MURATA_GRM033_H0P3 91.45,70.85 r180 bottom
C388 "Capacitor" C0201_MURATA_GRM033_H0P3 94.65,71.7 r180 bottom
C389 "Capacitor" C0201_MURATA_GRM033_H0P3 98.65,70.875 r0 bottom
C390 "Capacitor" C0201_MURATA_GRM033_H0P3 93.05,74.25 r0 bottom
C393 "Capacitor" C0201_MURATA_GRM033_H0P3 91.45,70 r180 bottom
C399 "Capacitor" C0201_MURATA_GRM033_H0P3 91.45,69.15 r180 bottom
C400 "Capacitor" C0201_MURATA_GRM033_H0P3 93.05,69.15 r0 bottom
C402 "Capacitor" C0201_MURATA_GRM033_H0P3 94.65,69.15 r0 bottom
C404 "Capacitor" C0201_MURATA_GRM033_H0P3 100.025,67.1 r90 bottom
C406 "Capacitor" C0201_MURATA_GRM033_H0P3 84.3,65.975 r0 top
C407 "Capacitor" C0201_MURATA_GRM033_H0P3 97.8,65.325 r90 bottom
C408 "Capacitor" C0201_MURATA_GRM033_H0P3 99.475,67.1 r90 bottom
C409 "Capacitor" C0201_MURATA_GRM033_H0P3 98.1,69.05 r0 bottom
C417 "Capacitor" C0201_MURATA_GRM033_H0P3 98.1,68.25 r0 bottom
C478 "Capacitor" C0402 115.225,90.175 r270 bottom
C479 "Capacitor" C0402 115.225,88.475 r270 bottom
C481 "Capacitor" C0402 109.2,86.35 r90 bottom
CN12 "" CON_MOLEX_53047-0210 67.475,64.05 r270 top
D5 "BAT60JFILM" DIO_SOD323 104.175,89.7 r90 bottom
D6 "DIODE_3P_DUAL_COMMON_CATHODE" DIO_SOT23 71.725,64.025 r270 top
L1 "Inductor" IND_2016_MURATA_LQM2MPN2R2NG0 58.295,83.175 r180 top
L2 "Inductor" IND_2520_TOKO_DFE252012P 66.415,82.45 r0 top
L3 "Inductor" IND_2016_MURATA_LQM2MPN2R2NG0 53.35,81.075 r90 top
L4 "Inductor" IND_2520_TOKO_DFE252012P 67.925,76.6 r0 top
L5 "Inductor" IND_2016_MURATA_LQM2MPN2R2NG0 50.525,74.7 r180 top
L6 "Inductor" IND_2016_MURATA_LQM2MPN2R2NG0 67,72 r0 top
L7 "Inductor" IND_2016_MURATA_LQM2MPN2R2NG0 52.9,70.05 r180 top
LD11 "LED_green" LED_0603_OSRAM_LG-Q396-PS-35_GREEN_1A2K_H0P4 42.887,67.327 r270 top
LNK1 "link_200" LINK200 60.6,84.123 r0 top
LNK2 "link_200" LINK200 76.219,76.687 r90 top
LNK4 "link_200" LINK200 50.35,81.125 r180 top
LNK7 "link_200" LINK200 72.45,75.35 r270 top
LNK8 "link_200" LINK200 48.2,77.498 r0 top
LNK11 "link_200" LINK200 74.6,71.44 r180 top
R2 "" R0402 55.08,67.695 r90 top
R3 "" R0402 77,59.85 r0 top
R26 "Resistor" R0402 117.025,78.625 r0 top
R27 "Resistor" R0402 81.975,69.45 r90 bottom
R37 "Resistor" R0402 113.1,88.225 r270 bottom
R44 "Resistor" R0402 106.975,88.85 r0 bottom
R46 "" R0402 62.65,81.998 r270 top
R49 "Resistor" R0402 113.1,89.95 r90 bottom
R57 "" R0402 63.35,67.95 r90 top
R59 "" R0402 52.98,67.695 r90 top
R60 "" R0402 54.03,67.695 r90 top
R64 "" R0402 79.15,67.45 r180 top
R66 "Resistor" R0402 68.675,60.845 r270 top
R67 "Resistor" R0402 71.075,66.375 r0 top
R81 "" R0402 62.663,84.348 r270 top
R94 "Resistor" R0201_H0P23 105.8,72.25 r0 bottom
R112 "Resistor" R0201_H0P23 99.028,74.45 r90 bottom
R161 "Resistor" R0402 90.6,80.1 r90 bottom
R162 "Resistor" R0402 84.7,80.2 r180 top
R196 "Resistor" R0402 96.55,63.175 r90 top
R197 "" R0402 99.55,65.725 r90 bottom
R199 "" R0402 75.5,75.4 r270 top
R210 "Resistor" R0402 42.887,69.52 r270 top
R248 "Resistor" R0402 107.85,90.525 r270 bottom
R260 "Resistor" R0402 60.33,82.13 r270 bottom
R261 "Resistor" R0402 61.305,82.13 r270 bottom
R272 "Resistor" R0402 85.925,67.5 r270 bottom
TP9 "Test Point" TP_SMD_1MM 110.529,85.747 r90 top
U2 "MT53E1G16D1ZW-046 AIT:C" ICC_TFBGA200_10X14P5_P080_H1P05 112.95,72.85 r90 top
U10 "IC_STM32MP257FAJ3" ICC_TFBGA361_16X16_P080 93.85,72.45 r0 top locked
U24 "eMMC_THGBMTG5D1LBAIL" ICC_P-WFBGA153_13X11P5_P050 110.525,90.6 r0 top locked
U26 "STPMIC25APQR" ICC_QFN56-EPAD_6P5X6P5_P040 60,75.8 r90 top
X1 "XTAL_2_PINS" CRY_NX2012SA_2P 76.525,66.65 r270 top
X2 "XTAL_4_PINS" CRY_NX1612SA_4P 76.098,61.176 r180 top

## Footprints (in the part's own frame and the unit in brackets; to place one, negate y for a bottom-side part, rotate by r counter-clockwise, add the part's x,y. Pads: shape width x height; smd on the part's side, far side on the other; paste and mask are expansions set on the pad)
C0201_H0P5 [mm] "MCD-01534"
  rect 0.4x0.5 smd mask+0: 1(-0.3,0) 2(0.3,0)
C0201_MURATA_GRM033_H0P3 [mm]
  rect 0.35x0.35 smd mask+0: 1(-0.275,0) 2(0.275,0)
C0402 [mm]
  rect 0.51x0.56 smd mask+0: 1(-0.45,0) 2(0.45,0)
C0603 [mm]
  rect 0.64x0.89 smd mask+0: 1(-0.7,0) 2(0.7,0)
  silkscreen extent -1.05,-0.55 1.02,0.55
C0805 [mm]
  rect 0.9x1.4 smd mask+0: 1(-0.85,0) 2(0.85,0)
  silkscreen extent -1.3,-0.77 1.3,0.77
CON_MOLEX_53047-0210 [mm]
  oval 1x1.3 hole 0.5 mask+0: 1(-0.625,0) 2(0.625,0)
  silkscreen extent -2.12,-1.15 2.13,2.05
CPOL_TCJ-B_1210_H210 [mm] "MCD-01791"
  rect 1.35x2.8 smd mask+0: 1(-1.375,0) 2(1.375,0)
  silkscreen extent -2.33,-1.68 1.85,1.68
CRY_NX1612SA_4P [mm] "MCD-02262"
  rect 0.75x0.6 smd mask+0: 1(-0.525,-0.375) 2(0.525,-0.375) 3(0.525,0.375) 4(-0.525,0.375)
  silkscreen extent -1.02,-0.8 0.03,0.6
CRY_NX2012SA_2P [mm]
  rect 1x1.25 smd mask+0: 1(-0.75,0) 2(0.75,0)
  silkscreen extent -1.05,-0.75 1.05,0.75
DIO_SOD323 [mm]
  rect 1.06x0.54 smd mask+0: 1(-1.07,0) 2(1.07,0)
  silkscreen extent -0.9,-0.72 0.9,0.72
DIO_SOT23 [mm]
  rect 1x1.4 smd mask+0: 1(-0.95,-1.1) 2(0.95,-1.1) 3(0,1.1)
  silkscreen extent -1.63,-0.82 1.63,0.82
ICC_P-WFBGA153_13X11P5_P050 [mm]
  round 0.23 smd mask+0: A1(-3.25,-3.25) A2(-3.25,-2.75) A3(-3.25,-2.25) A4(-3.25,-1.75) A5(-3.25,-1.25) A6(-3.25,-0.75) A7(-3.25,-0.25) A8(-3.25,0.25) A9(-3.25,0.75) A10(-3.25,1.25) A11(-3.25,1.75) A12(-3.25,2.25) A13(-3.25,2.75) A14(-3.25,3.25) B1(-2.75,-3.25) B2(-2.75,-2.75) B3(-2.75,-2.25) B4(-2.75,-1.75) B5(-2.75,-1.25) B6(-2.75,-0.75) B7(-2.75,-0.25) B8(-2.75,0.25) B9(-2.75,0.75) B10(-2.75,1.25) B11(-2.75,1.75) B12(-2.75,2.25) B13(-2.75,2.75) B14(-2.75,3.25) C1(-2.25,-3.25) C2(-2.25,-2.75) C3(-2.25,-2.25) C4(-2.25,-1.75) C5(-2.25,-1.25) C6(-2.25,-0.75) C7(-2.25,-0.25) C8(-2.25,0.25) C9(-2.25,0.75) C10(-2.25,1.25) C11(-2.25,1.75) C12(-2.25,2.25) C13(-2.25,2.75) C14(-2.25,3.25) D1(-1.75,-3.25) D2(-1.75,-2.75) D3(-1.75,-2.25) D4(-1.75,-1.75) D12(-1.75,2.25) D13(-1.75,2.75) D14(-1.75,3.25) E1(-1.25,-3.25) E2(-1.25,-2.75) E3(-1.25,-2.25) E5(-1.25,-1.25) E6(-1.25,-0.75) E7(-1.25,-0.25) E8(-1.25,0.25) E9(-1.25,0.75) E10(-1.25,1.25) E12(-1.25,2.25) E13(-1.25,2.75) E14(-1.25,3.25) F1(-0.75,-3.25) F2(-0.75,-2.75) F3(-0.75,-2.25) F5(-0.75,-1.25) F10(-0.75,1.25) F12(-0.75,2.25) F13(-0.75,2.75) F14(-0.75,3.25) G1(-0.25,-3.25) G2(-0.25,-2.75) G3(-0.25,-2.25) G5(-0.25,-1.25) G10(-0.25,1.25) G12(-0.25,2.25) G13(-0.25,2.75) G14(-0.25,3.25) H1(0.25,-3.25) H2(0.25,-2.75) H3(0.25,-2.25) H5(0.25,-1.25) H10(0.25,1.25) H12(0.25,2.25) H13(0.25,2.75) H14(0.25,3.25) J1(0.75,-3.25) J2(0.75,-2.75) J3(0.75,-2.25) J5(0.75,-1.25) J10(0.75,1.25) J12(0.75,2.25) J13(0.75,2.75) J14(0.75,3.25) K1(1.25,-3.25) K2(1.25,-2.75) K3(1.25,-2.25) K5(1.25,-1.25) K6(1.25,-0.75) K7(1.25,-0.25) K8(1.25,0.25) K9(1.25,0.75) K10(1.25,1.25) K12(1.25,2.25) K13(1.25,2.75) K14(1.25,3.25) L1(1.75,-3.25) L2(1.75,-2.75) L3(1.75,-2.25) L12(1.75,2.25) L13(1.75,2.75) L14(1.75,3.25) M1(2.25,-3.25) M2(2.25,-2.75) M3(2.25,-2.25) M4(2.25,-1.75) M5(2.25,-1.25) M6(2.25,-0.75) M7(2.25,-0.25) M8(2.25,0.25) M9(2.25,0.75) M10(2.25,1.25) M11(2.25,1.75) M12(2.25,2.25) M13(2.25,2.75) M14(2.25,3.25) N1(2.75,-3.25) N2(2.75,-2.75) N3(2.75,-2.25) N4(2.75,-1.75) N5(2.75,-1.25) N6(2.75,-0.75) N7(2.75,-0.25) N8(2.75,0.25) N9(2.75,0.75) N10(2.75,1.25) N11(2.75,1.75) N12(2.75,2.25) N13(2.75,2.75) N14(2.75,3.25) P1(3.25,-3.25) P2(3.25,-2.75) P3(3.25,-2.25) P4(3.25,-1.75) P5(3.25,-1.25) P6(3.25,-0.75) P7(3.25,-0.25) P8(3.25,0.25) P9(3.25,0.75) P10(3.25,1.25) P11(3.25,1.75) P12(3.25,2.25) P13(3.25,2.75) P14(3.25,3.25)
  silkscreen extent -6.78,-6.02 6.63,5.87
ICC_QFN56-EPAD_6P5X6P5_P040 [mm] "MCD-03000"
  rect 0.55x0.21 smd mask+0: 1(-3.245,2.6) 14(-3.245,-2.6) 29(3.245,-2.6) 42(3.245,2.6)
  rect 0.7x0.21 smd mask+0: 2(-3.17,2.2) 3(-3.17,1.8) 4(-3.17,1.4) 5(-3.17,1) 6(-3.17,0.6) 7(-3.17,0.2) 8(-3.17,-0.2) 9(-3.17,-0.6) 10(-3.17,-1) 11(-3.17,-1.4) 12(-3.17,-1.8) 13(-3.17,-2.2) 30(3.17,-2.2) 31(3.17,-1.8) 32(3.17,-1.4) 33(3.17,-1) 34(3.17,-0.6) 35(3.17,-0.2) 36(3.17,0.2) 37(3.17,0.6) 38(3.17,1) 39(3.17,1.4) 40(3.17,1.8) 41(3.17,2.2)
  rect 0.21x0.55 smd mask+0: 15(-2.6,-3.245) 28(2.6,-3.245) 43(2.6,3.245) 56(-2.6,3.245)
  rect 0.21x0.7 smd mask+0: 16(-2.2,-3.17) 17(-1.8,-3.17) 18(-1.4,-3.17) 19(-1,-3.17) 20(-0.6,-3.17) 21(-0.2,-3.17) 22(0.2,-3.17) 23(0.6,-3.17) 24(1,-3.17) 25(1.4,-3.17) 26(1.8,-3.17) 27(2.2,-3.17) 44(2.2,3.17) 45(1.8,3.17) 46(1.4,3.17) 47(1,3.17) 48(0.6,3.17) 49(0.2,3.17) 50(-0.2,3.17) 51(-0.6,3.17) 52(-1,3.17) 53(-1.4,3.17) 54(-1.8,3.17) 55(-2.2,3.17)
  rect 4.7x4.7 smd mask+0: 57(0,0)
  silkscreen extent -3.44,3 -3.01,3.42
ICC_TFBGA200_10X14P5_P080_H1P05 [mm]
  round 0.35 smd mask+0: A1(-4.4,6.825) A2(-3.6,6.825) A3(-2.8,6.825) A4(-2,6.825) A5(-1.2,6.825) A8(1.2,6.825) A9(2,6.825) A10(2.8,6.825) A11(3.6,6.825) A12(4.4,6.825) AA1(-4.4,-6.175) AA2(-3.6,-6.175) AA3(-2.8,-6.175) AA4(-2,-6.175) AA5(-1.2,-6.175) AA8(1.2,-6.175) AA9(2,-6.175) AA10(2.8,-6.175) AA11(3.6,-6.175) AA12(4.4,-6.175) AB1(-4.4,-6.825) AB2(-3.6,-6.825) AB3(-2.8,-6.825) AB4(-2,-6.825) AB5(-1.2,-6.825) AB8(1.2,-6.825) AB9(2,-6.825) AB10(2.8,-6.825) AB11(3.6,-6.825) AB12(4.4,-6.825) B1(-4.4,6.175) B2(-3.6,6.175) B3(-2.8,6.175) B4(-2,6.175) B5(-1.2,6.175) B8(1.2,6.175) B9(2,6.175) B10(2.8,6.175) B11(3.6,6.175) B12(4.4,6.175) C1(-4.4,5.525) C2(-3.6,5.525) C3(-2.8,5.525) C4(-2,5.525) C5(-1.2,5.525) C8(1.2,5.525) C9(2,5.525) C10(2.8,5.525) C11(3.6,5.525) C12(4.4,5.525) D1(-4.4,4.875) D2(-3.6,4.875) D3(-2.8,4.875) D4(-2,4.875) D5(-1.2,4.875) D8(1.2,4.875) D9(2,4.875) D10(2.8,4.875) D11(3.6,4.875) D12(4.4,4.875) E1(-4.4,4.225) E2(-3.6,4.225) E3(-2.8,4.225) E4(-2,4.225) E5(-1.2,4.225) E8(1.2,4.225) E9(2,4.225) E10(2.8,4.225) E11(3.6,4.225) E12(4.4,4.225) F1(-4.4,3.575) F2(-3.6,3.575) F3(-2.8,3.575) F4(-2,3.575) F5(-1.2,3.575) F8(1.2,3.575) F9(2,3.575) F10(2.8,3.575) F11(3.6,3.575) F12(4.4,3.575) G1(-4.4,2.925) G2(-3.6,2.925) G3(-2.8,2.925) G4(-2,2.925) G5(-1.2,2.925) G8(1.2,2.925) G9(2,2.925) G10(2.8,2.925) G11(3.6,2.925) G12(4.4,2.925) H1(-4.4,2.275) H2(-3.6,2.275) H3(-2.8,2.275) H4(-2,2.275) H5(-1.2,2.275) H8(1.2,2.275) H9(2,2.275) H10(2.8,2.275) H11(3.6,2.275) H12(4.4,2.275) J1(-4.4,1.625) J2(-3.6,1.625) J3(-2.8,1.625) J4(-2,1.625) J5(-1.2,1.625) J8(1.2,1.625) J9(2,1.625) J10(2.8,1.625) J11(3.6,1.65) J12(4.4,1.625) K1(-4.4,0.975) K2(-3.6,0.975) K3(-2.8,0.975) K4(-2,0.975) K5(-1.2,0.975) K8(1.2,0.975) K9(2,0.975) K10(2.8,0.975) K11(3.6,0.975) K12(4.4,0.975) N1(-4.4,-0.975) N2(-3.6,-0.975) N3(-2.8,-0.975) N4(-2,-0.975) N5(-1.2,-0.975) N8(1.2,-0.975) N9(2,-0.975) N10(2.8,-0.975) N11(3.6,-0.975) N12(4.4,-0.975) P1(-4.4,-1.625) P2(-3.6,-1.625) P3(-2.8,-1.625) P4(-2,-1.625) P5(-1.2,-1.625) P8(1.2,-1.625) P9(2,-1.625) P10(2.8,-1.625) P11(3.6,-1.625) P12(4.4,-1.625) R1(-4.4,-2.275) R2(-3.6,-2.275) R3(-2.8,-2.275) R4(-2,-2.275) R5(-1.2,-2.275) R8(1.2,-2.275) R9(2,-2.275) R10(2.8,-2.275) R11(3.6,-2.275) R12(4.4,-2.275) T1(-4.4,-2.925) T2(-3.6,-2.925) T3(-2.8,-2.925) T4(-2,-2.925) T5(-1.2,-2.925) T8(1.2,-2.925) T9(2,-2.925) T10(2.8,-2.925) T11(3.6,-2.925) T12(4.4,-2.925) U1(-4.4,-3.575) U2(-3.6,-3.575) U3(-2.8,-3.575) U4(-2,-3.575) U5(-1.2,-3.575) U8(1.2,-3.575) U9(2,-3.575) U10(2.8,-3.575) U11(3.6,-3.575) U12(4.4,-3.575) V1(-4.4,-4.225) V2(-3.6,-4.225) V3(-2.8,-4.225) V4(-2,-4.225) V5(-1.2,-4.225) V8(1.2,-4.225) V9(2,-4.225) V10(2.8,-4.225) V11(3.6,-4.225) V12(4.4,-4.225) W1(-4.4,-4.875) W2(-3.6,-4.875) W3(-2.8,-4.875) W4(-2,-4.875) W5(-1.2,-4.875) W8(1.2,-4.875) W9(2,-4.875) W10(2.8,-4.875) W11(3.6,-4.875) W12(4.4,-4.875) Y1(-4.4,-5.525) Y2(-3.6,-5.525) Y3(-2.8,-5.525) Y4(-2,-5.525) Y5(-1.2,-5.525) Y8(1.2,-5.525) Y9(2,-5.525) Y10(2.8,-5.525) Y11(3.6,-5.525) Y12(4.4,-5.525)
  silkscreen extent -5.2,-7.3 5.05,7.45
ICC_TFBGA361_16X16_P080 [mm] "MCD-04441"
  round 0.3 smd mask+0: A1(-7.2,7.2) A2(-6.4,7.2) A3(-5.6,7.2) A4(-4.8,7.2) A5(-4,7.2) A6(-3.2,7.2) A7(-2.4,7.2) A8(-1.6,7.2) A9(-0.8,7.2) A10(0,7.2) A11(0.8,7.2) A12(1.6,7.2) A13(2.4,7.2) A14(3.2,7.2) A15(4,7.2) A16(4.8,7.2) A17(5.6,7.2) A18(6.4,7.2) A19(7.2,7.2) B1(-7.2,6.4) B2(-6.4,6.4) B3(-5.6,6.4) B4(-4.8,6.4) B5(-4,6.4) B6(-3.2,6.4) B7(-2.4,6.4) B8(-1.6,6.4) B9(-0.8,6.4) B10(0,6.4) B11(0.8,6.4) B12(1.6,6.4) B13(2.4,6.4) B14(3.2,6.4) B15(4,6.4) B16(4.8,6.4) B17(5.6,6.4) B18(6.4,6.4) B19(7.2,6.4) C1(-7.2,5.6) C2(-6.4,5.6) C3(-5.6,5.6) C4(-4.8,5.6) C5(-4,5.6) C6(-3.2,5.6) C7(-2.4,5.6) C8(-1.6,5.6) C9(-0.8,5.6) C10(0,5.6) C11(0.8,5.6) C12(1.6,5.6) C13(2.4,5.6) C14(3.2,5.6) C15(4,5.6) C16(4.8,5.6) C17(5.6,5.6) C18(6.4,5.6) C19(7.2,5.6) D1(-7.2,4.8) D2(-6.4,4.8) D3(-5.6,4.8) D4(-4.8,4.8) D5(-4,4.8) D6(-3.2,4.8) D7(-2.4,4.8) D8(-1.6,4.8) D9(-0.8,4.8) D10(0,4.8) D11(0.8,4.8) D12(1.6,4.8) D13(2.4,4.8) D14(3.2,4.8) D15(4,4.8) D16(4.8,4.8) D17(5.6,4.8) D18(6.4,4.8) D19(7.2,4.8) E1(-7.2,4) E2(-6.4,4) E3(-5.6,4) E4(-4.8,4) E5(-4,4) E6(-3.2,4) E7(-2.4,4) E8(-1.6,4) E9(-0.8,4) E10(0,4) E11(0.8,4) E12(1.6,4) E13(2.4,4) E14(3.2,4) E15(4,4) E16(4.8,4) E17(5.6,4) E18(6.4,4) E19(7.2,4) F1(-7.2,3.2) F2(-6.4,3.2) F3(-5.6,3.2) F4(-4.8,3.2) F5(-4,3.2) F6(-3.2,3.2) F7(-2.4,3.2) F8(-1.6,3.2) F9(-0.8,3.2) F10(0,3.2) F11(0.8,3.2) F12(1.6,3.2) F13(2.4,3.2) F14(3.2,3.2) F15(4,3.2) F16(4.8,3.2) F17(5.6,3.2) F18(6.4,3.2) F19(7.2,3.2) G1(-7.2,2.4) G2(-6.4,2.4) G3(-5.6,2.4) G4(-4.8,2.4) G5(-4,2.4) G6(-3.2,2.4) G7(-2.4,2.4) G8(-1.6,2.4) G9(-0.8,2.4) G10(0,2.4) G11(0.8,2.4) G12(1.6,2.4) G13(2.4,2.4) G14(3.2,2.4) G15(4,2.4) G16(4.8,2.4) G17(5.6,2.4) G18(6.4,2.4) G19(7.2,2.4) H1(-7.2,1.6) H2(-6.4,1.6) H3(-5.6,1.6) H4(-4.8,1.6) H5(-4,1.6) H6(-3.2,1.6) H7(-2.4,1.6) H8(-1.6,1.6) H9(-0.8,1.6) H10(0,1.6) H11(0.8,1.6) H12(1.6,1.6) H13(2.4,1.6) H14(3.2,1.6) H15(4,1.6) H16(4.8,1.6) H17(5.6,1.6) H18(6.4,1.6) H19(7.2,1.6) J1(-7.2,0.8) J2(-6.4,0.8) J3(-5.6,0.8) J4(-4.8,0.8) J5(-4,0.8) J6(-3.2,0.8) J7(-2.4,0.8) J8(-1.6,0.8) J9(-0.8,0.8) J10(0,0.8) J11(0.8,0.8) J12(1.6,0.8) J13(2.4,0.8) J14(3.2,0.8) J15(4,0.8) J16(4.8,0.8) J17(5.6,0.8) J18(6.4,0.8) J19(7.2,0.8) K1(-7.2,0) K2(-6.4,0) K3(-5.6,0) K4(-4.8,0) K5(-4,0) K6(-3.2,0) K7(-2.4,0) K8(-1.6,0) K9(-0.8,0) K10(0,0) K11(0.8,0) K12(1.6,0) K13(2.4,0) K14(3.2,0) K15(4,0) K16(4.8,0) K17(5.6,0) K18(6.4,0) K19(7.2,0) L1(-7.2,-0.8) L2(-6.4,-0.8) L3(-5.6,-0.8) L4(-4.8,-0.8) L5(-4,-0.8) L6(-3.2,-0.8) L7(-2.4,-0.8) L8(-1.6,-0.8) L9(-0.8,-0.8) L10(0,-0.8) L11(0.8,-0.8) L12(1.6,-0.8) L13(2.4,-0.8) L14(3.2,-0.8) L15(4,-0.8) L16(4.8,-0.8) L17(5.6,-0.8) L18(6.4,-0.8) L19(7.2,-0.8) M1(-7.2,-1.6) M2(-6.4,-1.6) M3(-5.6,-1.6) M4(-4.8,-1.6) M5(-4,-1.6) M6(-3.2,-1.6) M7(-2.4,-1.6) M8(-1.6,-1.6) M9(-0.8,-1.6) M10(0,-1.6) M11(0.8,-1.6) M12(1.6,-1.6) M13(2.4,-1.6) M14(3.2,-1.6) M15(4,-1.6) M16(4.8,-1.6) M17(5.6,-1.6) M18(6.4,-1.6) M19(7.2,-1.6) N1(-7.2,-2.4) N2(-6.4,-2.4) N3(-5.6,-2.4) N4(-4.8,-2.4) N5(-4,-2.4) N6(-3.2,-2.4) N7(-2.4,-2.4) N8(-1.6,-2.4) N9(-0.8,-2.4) N10(0,-2.4) N11(0.8,-2.4) N12(1.6,-2.4) N13(2.4,-2.4) N14(3.2,-2.4) N15(4,-2.4) N16(4.8,-2.4) N17(5.6,-2.4) N18(6.4,-2.4) N19(7.2,-2.4) P1(-7.2,-3.2) P2(-6.4,-3.2) P3(-5.6,-3.2) P4(-4.8,-3.2) P5(-4,-3.2) P6(-3.2,-3.2) P7(-2.4,-3.2) P8(-1.6,-3.2) P9(-0.8,-3.2) P10(0,-3.2) P11(0.8,-3.2) P12(1.6,-3.2) P13(2.4,-3.2) P14(3.2,-3.2) P15(4,-3.2) P16(4.8,-3.2) P17(5.6,-3.2) P18(6.4,-3.2) P19(7.2,-3.2) R1(-7.2,-4) R2(-6.4,-4) R3(-5.6,-4) R4(-4.8,-4) R5(-4,-4) R6(-3.2,-4) R7(-2.4,-4) R8(-1.6,-4) R9(-0.8,-4) R10(0,-4) R11(0.8,-4) R12(1.6,-4) R13(2.4,-4) R14(3.2,-4) R15(4,-4) R16(4.8,-4) R17(5.6,-4) R18(6.4,-4) R19(7.2,-4) T1(-7.2,-4.8) T2(-6.4,-4.8) T3(-5.6,-4.8) T4(-4.8,-4.8) T5(-4,-4.8) T6(-3.2,-4.8) T7(-2.4,-4.8) T8(-1.6,-4.8) T9(-0.8,-4.8) T10(0,-4.8) T11(0.8,-4.8) T12(1.6,-4.8) T13(2.4,-4.8) T14(3.2,-4.8) T15(4,-4.8) T16(4.8,-4.8) T17(5.6,-4.8) T18(6.4,-4.8) T19(7.2,-4.8) U1(-7.2,-5.6) U2(-6.4,-5.6) U3(-5.6,-5.6) U4(-4.8,-5.6) U5(-4,-5.6) U6(-3.2,-5.6) U7(-2.4,-5.6) U8(-1.6,-5.6) U9(-0.8,-5.6) U10(0,-5.6) U11(0.8,-5.6) U12(1.6,-5.6) U13(2.4,-5.6) U14(3.2,-5.6) U15(4,-5.6) U16(4.8,-5.6) U17(5.6,-5.6) U18(6.4,-5.6) U19(7.2,-5.6) V1(-7.2,-6.4) V2(-6.4,-6.4) V3(-5.6,-6.4) V4(-4.8,-6.4) V5(-4,-6.4) V6(-3.2,-6.4) V7(-2.4,-6.4) V8(-1.6,-6.4) V9(-0.8,-6.4) V10(0,-6.4) V11(0.8,-6.4) V12(1.6,-6.4) V13(2.4,-6.4) V14(3.2,-6.4) V15(4,-6.4) V16(4.8,-6.4) V17(5.6,-6.4) V18(6.4,-6.4) V19(7.2,-6.4) W1(-7.2,-7.2) W2(-6.4,-7.2) W3(-5.6,-7.2) W4(-4.8,-7.2) W5(-4,-7.2) W6(-3.2,-7.2) W7(-2.4,-7.2) W8(-1.6,-7.2) W9(-0.8,-7.2) W10(0,-7.2) W11(0.8,-7.2) W12(1.6,-7.2) W13(2.4,-7.2) W14(3.2,-7.2) W15(4,-7.2) W16(4.8,-7.2) W17(5.6,-7.2) W18(6.4,-7.2) W19(7.2,-7.2)
  silkscreen extent -8,-8 8,8
IND_2016_MURATA_LQM2MPN2R2NG0 [mm]
  rect 0.8x1.8 smd mask+0: 1(-0.8,0) 2(0.8,0)
  silkscreen extent -0.28,-0.87 0.28,0.87
IND_2520_TOKO_DFE252012P [mm]
  rect 0.8x2 smd mask+0: 1(-1,0) 2(1,0)
  silkscreen extent -1.35,-1.12 1.35,1.12
LED_0603_OSRAM_LG-Q396-PS-35_GREEN_1A2K_H0P4 [mm]
  rect 0.8x0.8 smd mask+0: 1(-0.75,0) 2(0.75,0)
  silkscreen extent -0.85,-0.53 1.28,0.53
LINK200 [mm]
  rect 0.2x0.35 smd paste-10 mask+0: 1(0,-0.225) 2(0,0.225)
R0201_H0P23 [mm]
  rect 0.4x0.5 smd mask+0: 1(-0.3,0) 2(0.3,0)
R0402 [mm]
  rect 0.51x0.7 smd mask+0: 1(-0.45,0) 2(0.45,0)
SWI_WE_434121025816 [mm] "MCD-03492"
  rect 1.5x1.4 smd: 1(-3.25,0) 2(3.25,0)
  silkscreen extent -3,-1.95 3,1.95
TP_SMD_1MM [mm]
  round 1 smd paste-10 mask+0: 1(0.253,1.029)
  silkscreen extent -0.7,-0.7 0.7,0.7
